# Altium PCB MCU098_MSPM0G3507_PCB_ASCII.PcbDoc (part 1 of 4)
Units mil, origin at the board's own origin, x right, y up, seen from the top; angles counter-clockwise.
Board outline 2310.03 x 4205.03 mil, 4 copper layers (Top Layer, VCC Layer, GND Layer, Bottom Layer), stack 62.4 mil thick; 260 components, 182 nets, 835 pads, 237 vias.
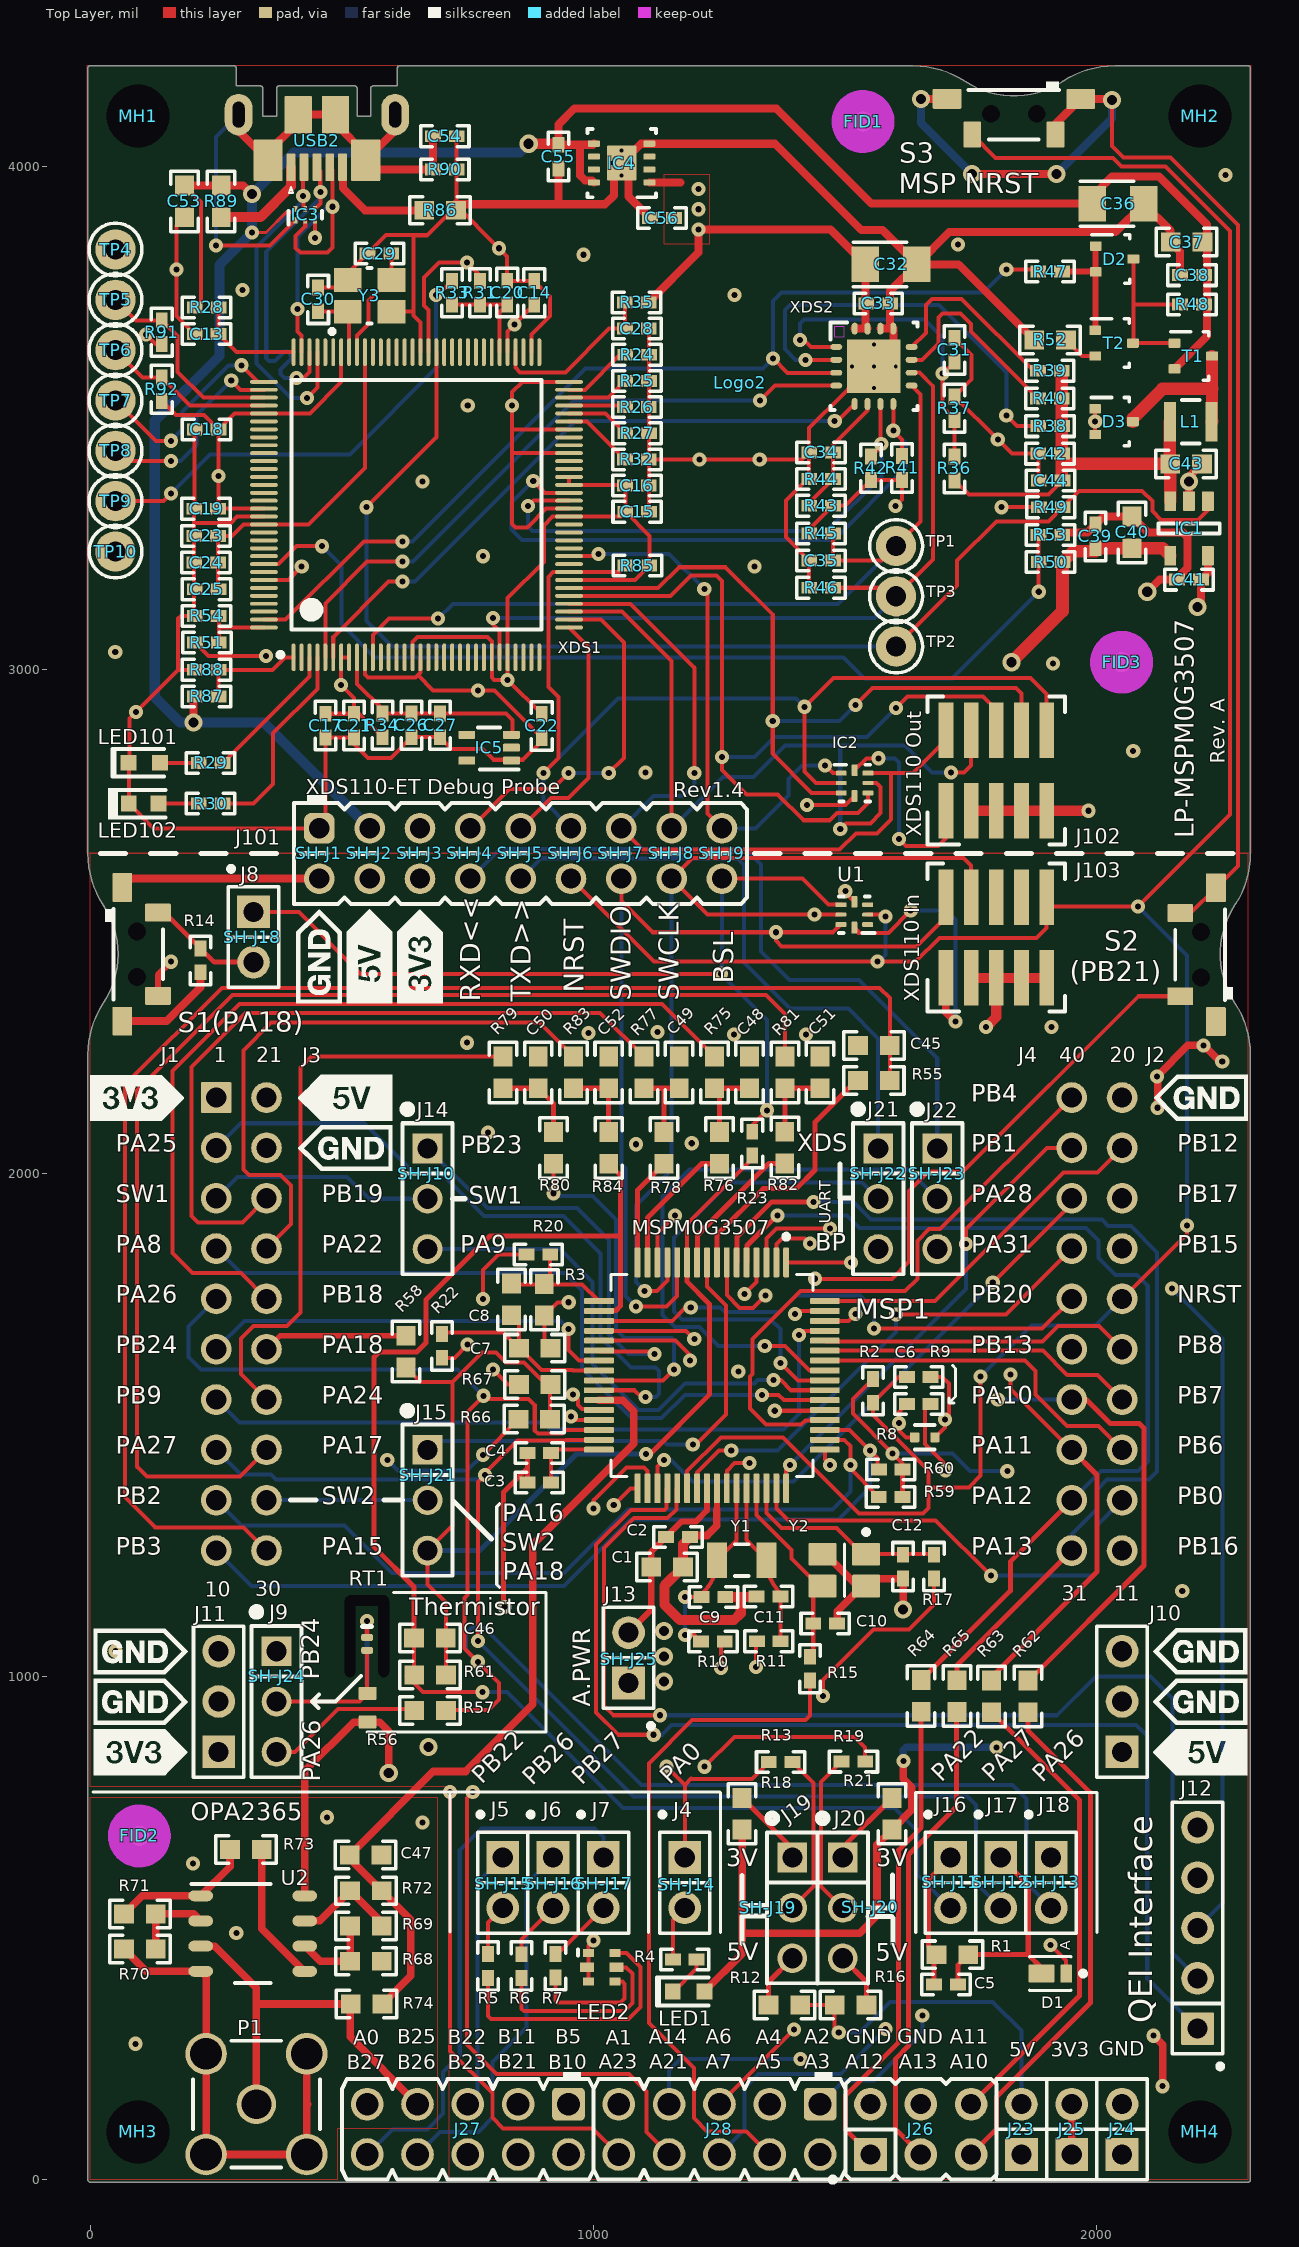
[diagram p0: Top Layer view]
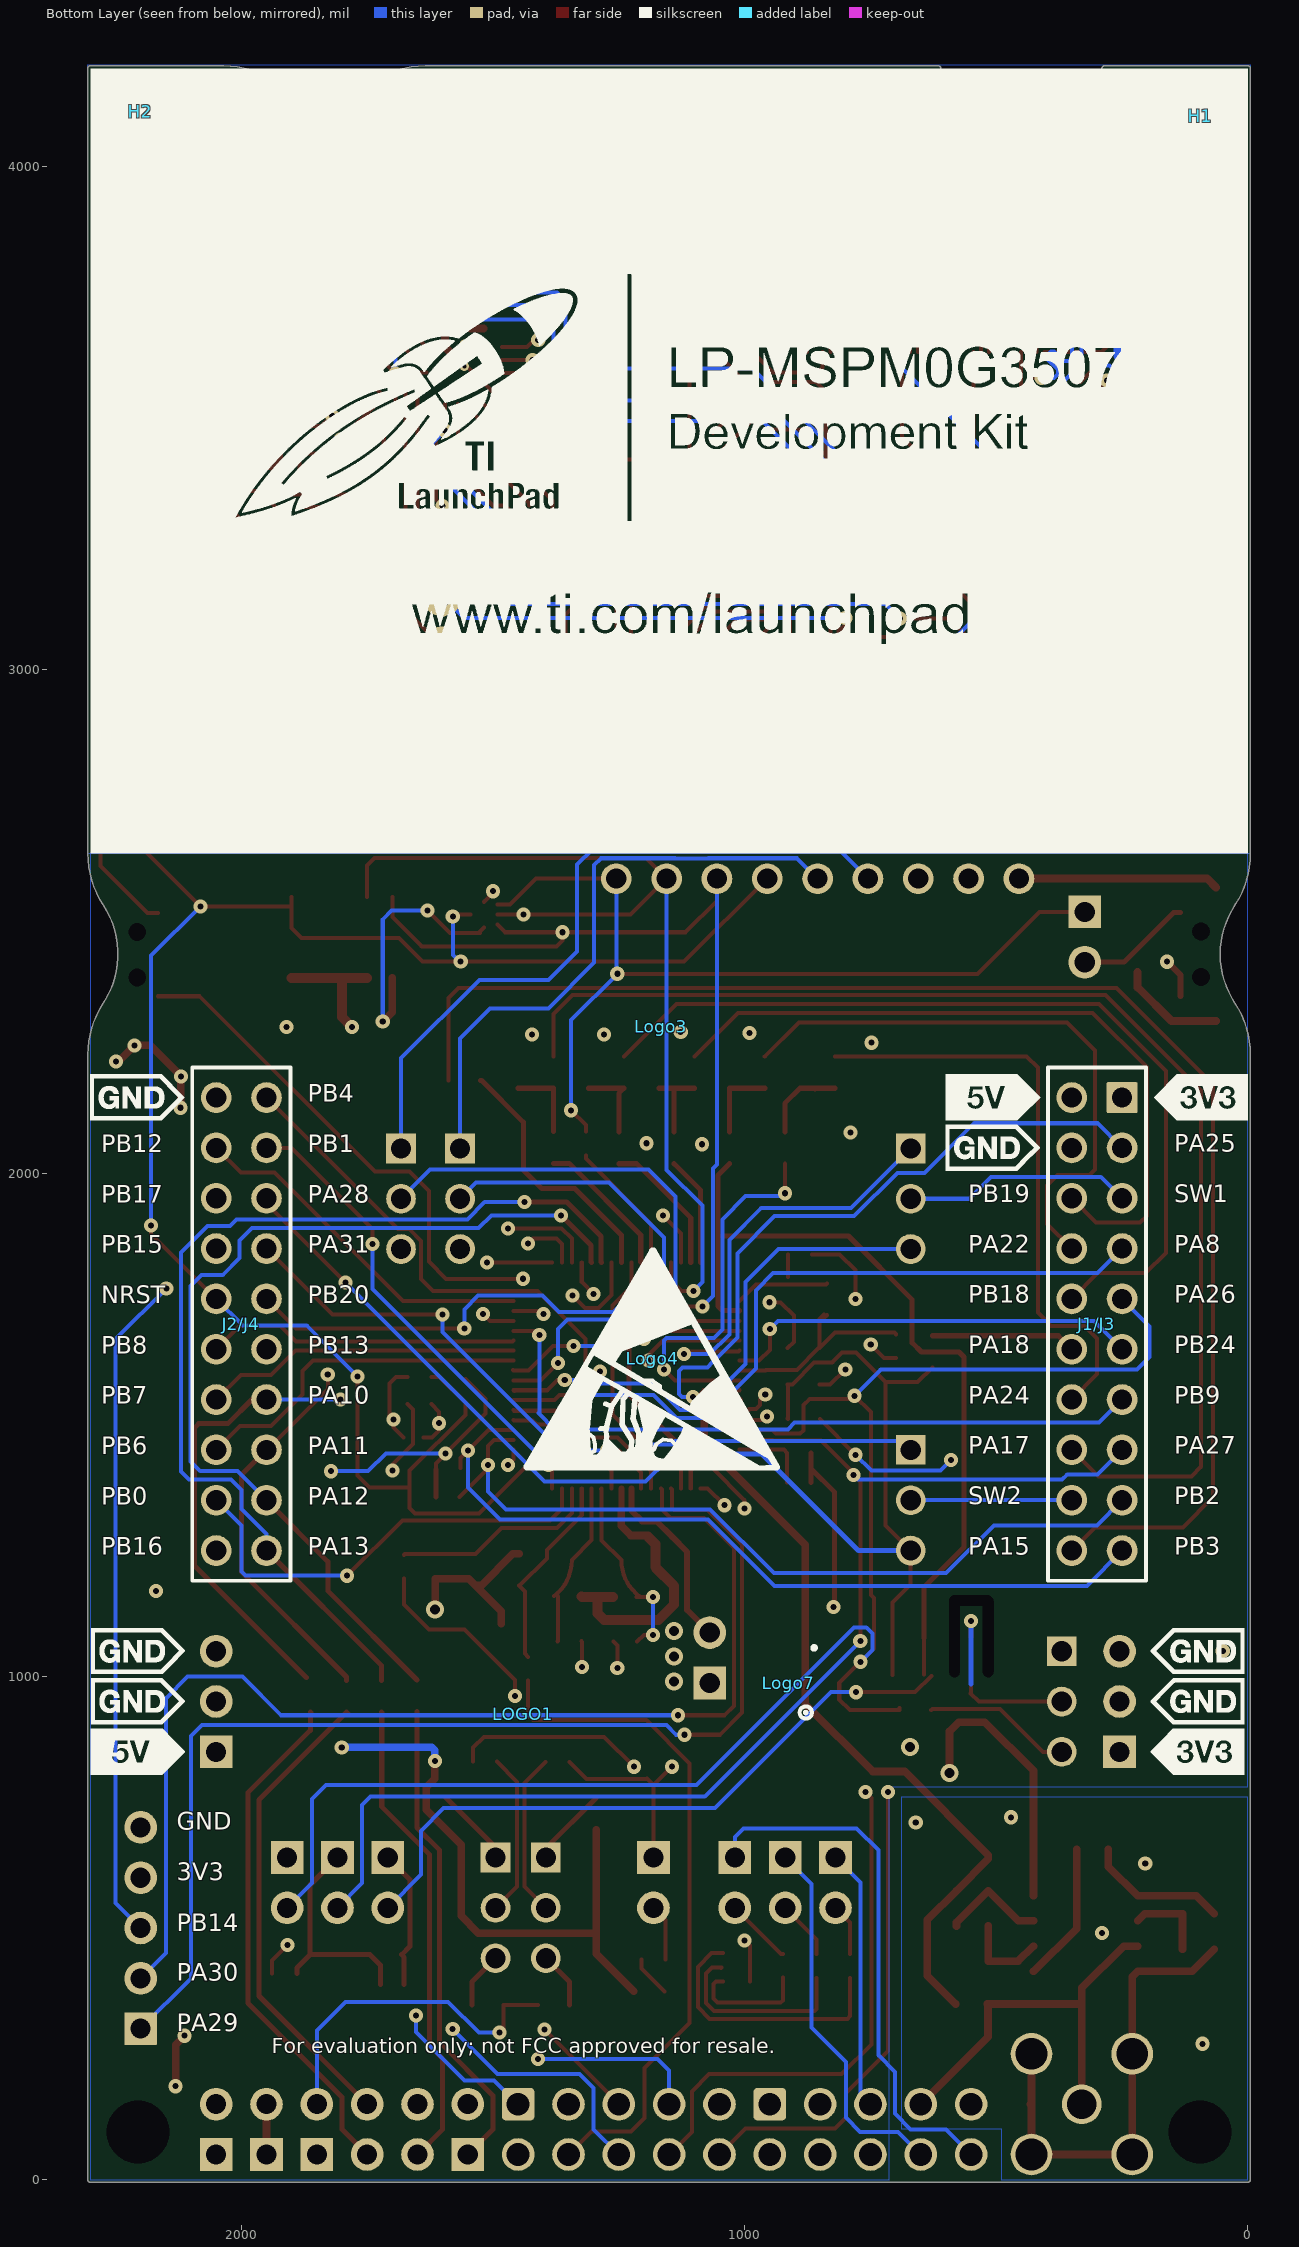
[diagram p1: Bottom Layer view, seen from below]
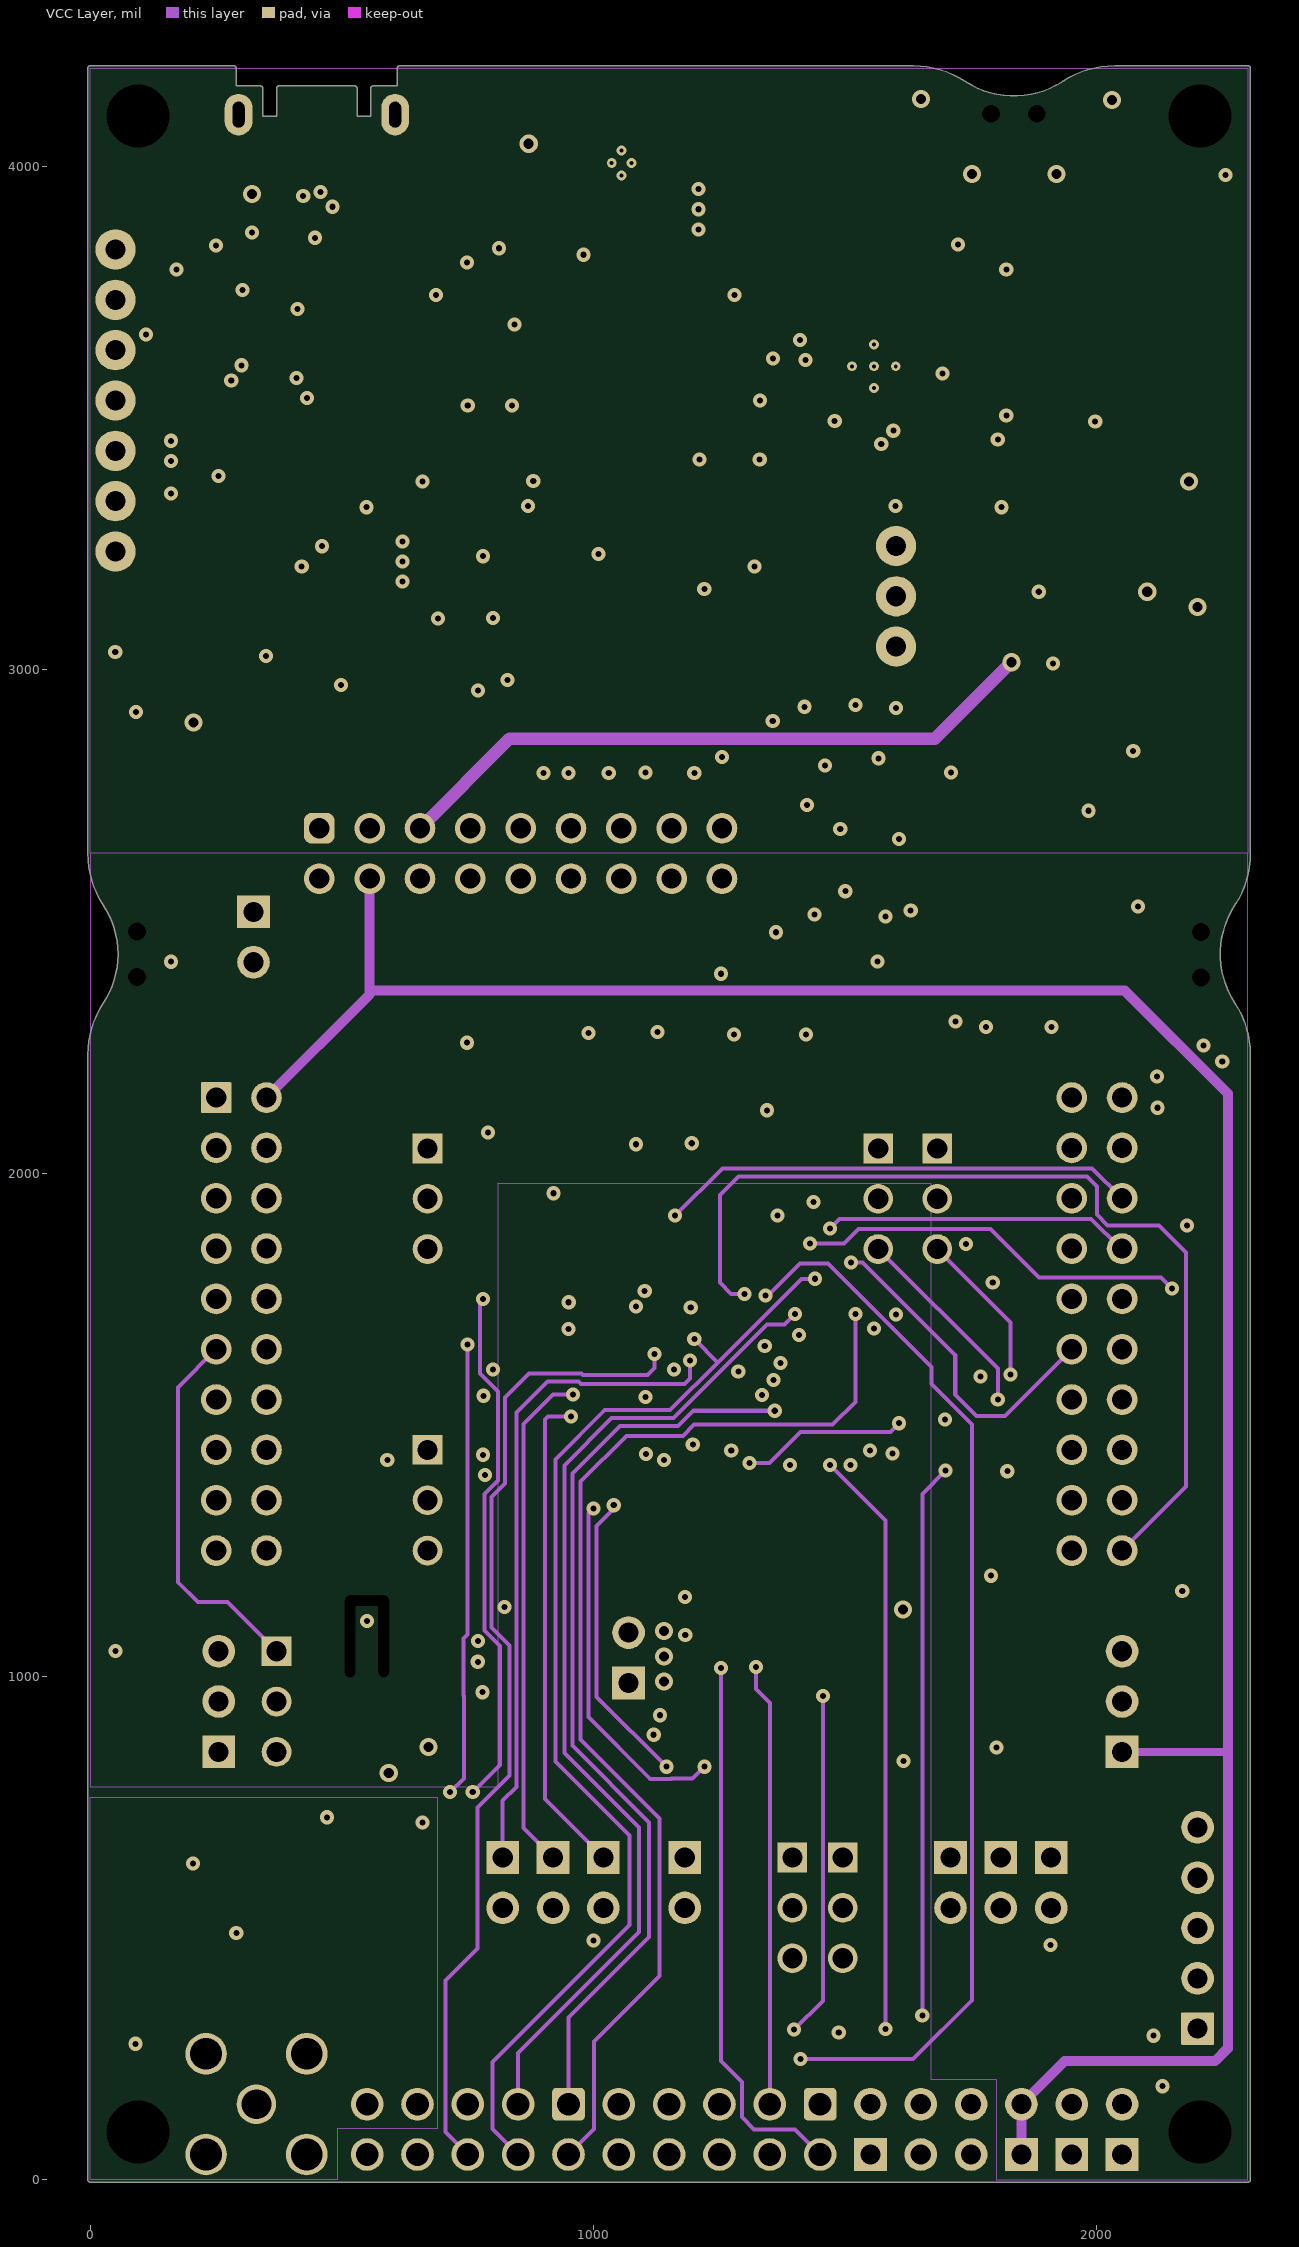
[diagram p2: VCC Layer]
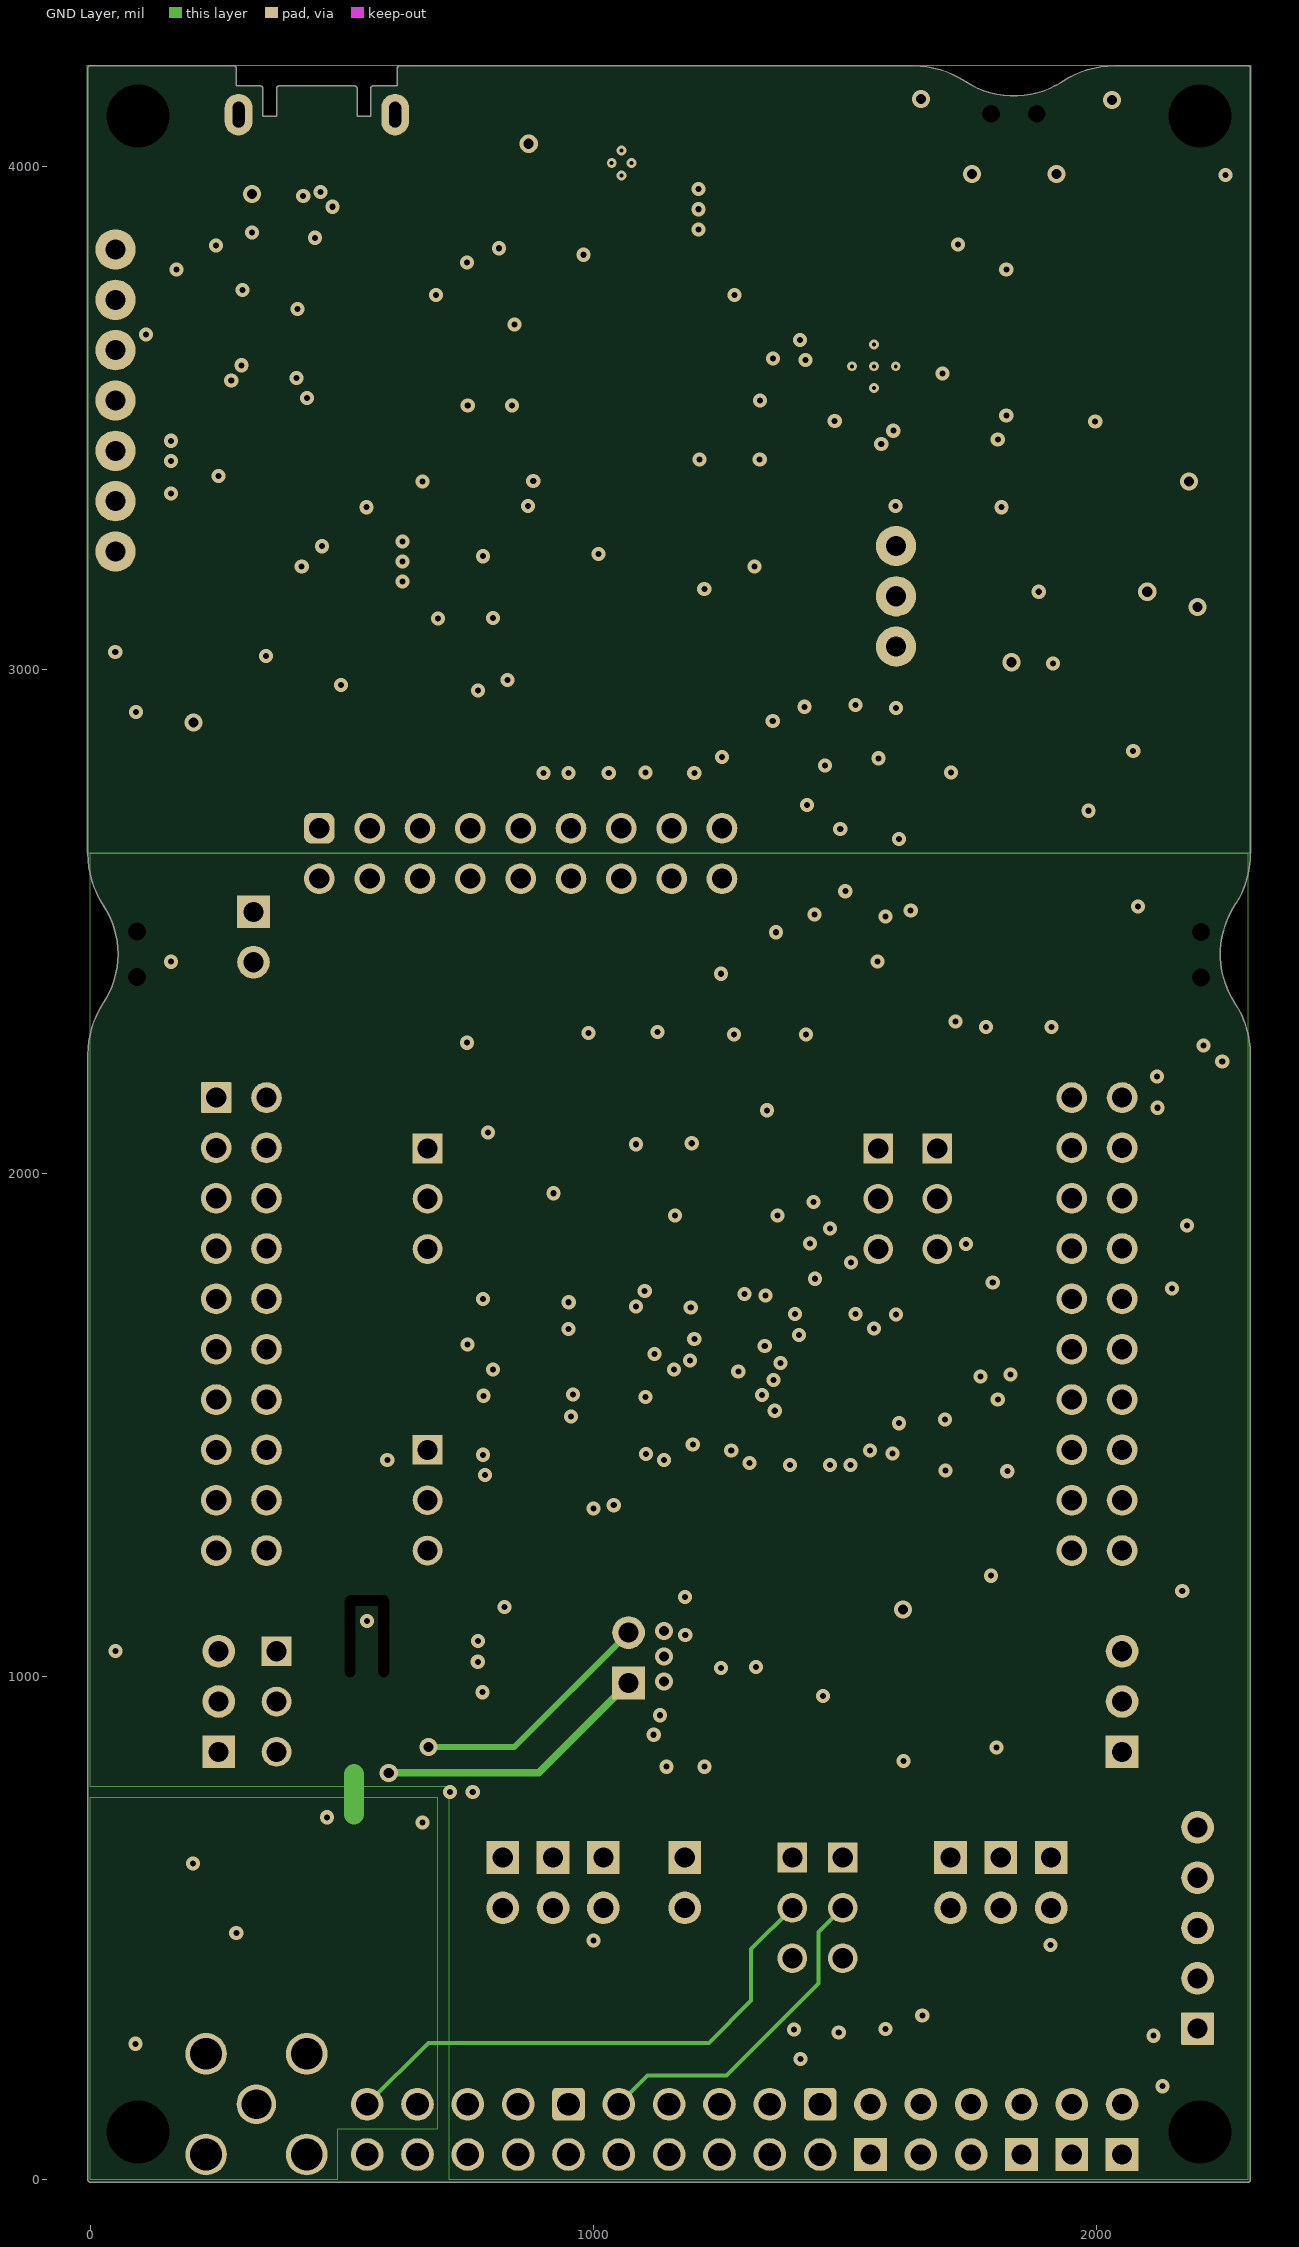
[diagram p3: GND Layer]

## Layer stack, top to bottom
Top Solder: solder mask 0.9843, SM-004, Dk 4
Top Layer: signal copper 1.4
Dielectric 2: core 8.4, FR-4, Dk 4.2
VCC Layer: signal copper 1.4
Dielectric1: prepreg 40, FR-4, Dk 4.2
GND Layer: signal copper 1.4
Dielectric 3: core 8.4, FR-4, Dk 4.2
Bottom Layer: signal copper 1.4
Bottom Solder: solder mask 0.9843, SM-004, Dk 4

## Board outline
-5.01,0 -5.01,2235 cw(c181.67,2235) 25.81,2337.76 ccw(c-121.67,2435) 25.83,2337.79 ccw(c-121.67,2435) 54.99,2435 ccw(c-121.67,2435) 25.88,2532.14 cw(c30,2535) 25.81,2532.24 cw(c181.67,2635) -5.01,2635 -5.01,4195 cw(c0,4195) 0,4200.02 285,4200.02 cw(c285,4195) 290.02,4195 290.02,4160.02 338,4160.02 cw(c338,4155) 343.02,4155 343.02,4100.02 369.99,4100.02 369.99,4155 cw(c375,4155) 375,4160.02 525,4160.02 cw(c525,4155) 530.02,4155 530.02,4100.02 556.99,4100.02 556.99,4155 cw(c562,4155) 562,4160.02 609.99,4160.02 609.99,4195 cw(c615,4195) 615,4200.02 1635,4200.02 cw(c1635,4013.33) 1737.76,4169.19 ccw(c1835,4316.67) 1737.79,4169.17 ccw(c1835,4316.67) 1932.14,4169.12 ccw(c1835,4316.67) 1932.24,4169.18 1932.24,4169.19 cw(c2035,4013.33) 2035,4200.02 2300,4200.02 cw(c2300,4195) 2305.02,4195 2305.02,2635 cw(c2118.33,2635) 2274.19,2532.24 cw(c2270,2535) 2274.17,2532.21 cw(c2421.67,2435) 2274.19,2532.24 2274.17,2532.21 ccw(c2421.67,2435) 2274.12,2337.86 cw(c2270,2335) 2274.19,2337.76 cw(c2118.33,2235) 2305.02,2235 2305.02,0.03 cw(c2300,0) 2305.02,0 2305.02,2235 2305.02,0.03 2305.02,0 cw(c2300,0) 2300,-5.01 0,-5.01 cw(c0,0)

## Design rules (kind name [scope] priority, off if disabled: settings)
AcuteAngle [All] p0: scope1count=1 scope1_0_kind=Board scope1_0_value=Board scope2count=1 scope2_0_kind=Board scope2_0_value=Board commentlength=0 minimum=4.50000000000000E+0001
AcuteAngle [All] p1: minimum=4.50000000000000E+0001 checktracksonly=FALSE
AssemblyTestPointUsage [All] p0: scope1count=1 scope1_0_kind=Board scope1_0_value=Board scope2count=1 scope2_0_kind=Board scope2_0_value=Board commentlength=0
AssemblyTestPointUsage [All] p1: valid=2
AssemblyTestpoint [All] p0: scope1count=1 scope1_0_kind=Board scope1_0_value=Board scope2count=1 scope2_0_kind=Board scope2_0_value=Board commentlength=0
BoardOutlineClearance BoardOutlineClearance_MountingHoles [All] p0 off: scope1count=1 scope1_0_kind=Board scope1_0_value=Board scope2count=1 scope2_0_kind=Board scope2_0_value=Board commentlength=86 gap=15 // Protel DXP Scope 1 Expression Was: OnCopper and InComponentClass('Mounting Holes')
BoardOutlineClearance BoardOutlineClearance_Poly [All] p0 off: scope1count=1 scope1_0_kind=Board scope1_0_value=Board scope2count=1 scope2_0_kind=Board scope2_0_value=Board commentlength=58 gap=15 // Protel DXP Scope 1 Expression Was: OnCopper and IsPoly
BoardOutlineClearance [All] p0 off: scope1count=1 scope1_0_kind=Board scope1_0_value=Board scope2count=1 scope2_0_kind=Board scope2_0_value=Board commentlength=172 gap=10 // Protel DXP Scope 1 Expression Was: OnCopper and Not InComponentClass('Logo') and not InComponentClass('FiducialMark') and not InRegion(1000,500,4000,800) and not InPoly
BoardOutlineClearance BoardOutlineClearance_MountingHoles [OnCopper and InComponentClass('Mounting Holes')] p1: gap=15 ignorepadtopadclearanceinfootprint=FALSE
BoardOutlineClearance BoardOutlineClearance_Poly [OnCopper and IsPoly] p2: gap=15 ignorepadtopadclearanceinfootprint=FALSE
BoardOutlineClearance [OnCopper and Not InComponentClass('Logo') and not InComponentClass('FiducialMark') and not InRegion(1000,500,4000,800) and not InPoly] p3: gap=10 ignorepadtopadclearanceinfootprint=FALSE
Clearance SMD [All] p0 off: scope1count=1 scope1_0_kind=Board scope1_0_value=Board scope2count=1 scope2_0_kind=Board scope2_0_value=Board commentlength=76 gap=10 // Protel DXP Scope 1 Expression Was: InNamedPolygon('GND_LAYER_GND_P-001')
Clearance Clearance_Keepouts [All] p0 off: scope1count=1 scope1_0_kind=Board scope1_0_value=Board scope2count=1 scope2_0_kind=Board scope2_0_value=Board commentlength=99 gap=0 // Protel DXP Scope 2 Expression Was: ((IsTrack Or IsArc) And Not InPoly) And IsFree and IsKeepOut
Clearance Clearance_Poly [All] p0 off: scope1count=1 scope1_0_kind=Board scope1_0_value=Board scope2count=1 scope2_0_kind=Board scope2_0_value=Board commentlength=48 gap=14 // Protel DXP Scope 1 Expression Was: InPolygon
Clearance [All] p0: scope1count=1 scope1_0_kind=Board scope1_0_value=Board scope2count=1 scope2_0_kind=Board scope2_0_value=Board commentlength=0 gap=6
Clearance Clearance_FiducialMark [All] p0 off: scope1count=1 scope1_0_kind=Board scope1_0_value=Board scope2count=1 scope2_0_kind=Board scope2_0_value=Board commentlength=81 gap=0 // Protel DXP Scope 2 Expression Was: IsPad and InComponentClass('FiducialMark')
Clearance SMD [InNamedPolygon('GND_LAYER_GND_P-001')] p1: gap=10 ignorepadtopadclearanceinfootprint=FALSE except(0: Arc-Hole Track-Hole SMDPad-Hole THPad-Hole Via-Hole Fill-Hole Poly-Hole Region-Hole Text-Hole; 20: SMDPad-SMDPad SMDPad-THPad SMDPad-Via SMDPad-Fill SMDPad-Poly SMDPad-Region SMDPad-Text)
Clearance Clearance_FiducialMark [IsKeepOut and InComponentClass('FiducialMark') vs IsPad and InComponentClass('FiducialMark')] p2: gap=0 ignorepadtopadclearanceinfootprint=FALSE
Clearance Clearance_Keepouts [((IsTrack Or IsArc) And Not InPoly) And IsFree and IsKeepOut vs ((IsTrack Or IsArc) And Not InPoly) And IsFree and IsKeepOut] p3: gap=0 ignorepadtopadclearanceinfootprint=FALSE
Clearance Clearance_Poly [InPolygon] p4: gap=14 ignorepadtopadclearanceinfootprint=FALSE except(0: Arc-Hole Track-Hole SMDPad-Hole THPad-Hole Via-Hole Fill-Hole Poly-Hole Region-Hole Text-Hole; 12: Arc-Fill Arc-Poly Arc-Region Track-Fill Track-Poly Track-Region; 15: THPad-THPad; 17: SMDPad-Fill SMDPad-Poly SMDPad-Region)
Clearance [All] p5: gap=6 ignorepadtopadclearanceinfootprint=FALSE
ComponentClearance ComponentClearance_MountingHoles_FiducialMarks [All] p0: scope1count=1 scope1_0_kind=ComponentClass scope1_0_value="Mounting Holes" scope2count=1 scope2_0_kind=ComponentClass scope2_0_value=FiducialMark commentlength=0 gap=0 collisioncheckmode=3
ComponentClearance ComponentClearance_Shunt [All] p0: scope1count=1 scope1_0_kind=ComponentClass scope1_0_value=Header scope2count=1 scope2_0_kind=ComponentClass scope2_0_value=Shunt commentlength=0 gap=0 collisioncheckmode=3
ComponentClearance ComponentClearance_Logo [All] p0: scope1count=1 scope1_0_kind=ComponentClass scope1_0_value=Logo scope2count=1 scope2_0_kind=Board scope2_0_value=Board commentlength=0 gap=0 collisioncheckmode=3
ComponentClearance ComponentClearance_ScrewToNut [All] p0 off: scope1count=1 scope1_0_kind=Board scope1_0_value=Board scope2count=1 scope2_0_kind=Board scope2_0_value=Board commentlength=71 gap=5 collisioncheckmode=3 // Protel DXP Scope 2 Expression Was: (HasFootprint('Keystone_1902C'))
ComponentClearance ComponentClearance_MountingHoles [All] p0: scope1count=1 scope1_0_kind=ComponentClass scope1_0_value="Mounting Holes" scope2count=1 scope2_0_kind=Board scope2_0_value=Board commentlength=0 gap=250 collisioncheckmode=3
ComponentClearance ComponentClearance_SmallPassives [All] p0 off: scope1count=1 scope1_0_kind=Board scope1_0_value=Board scope2count=1 scope2_0_kind=Board scope2_0_value=Board commentlength=508 gap=0 collisioncheckmode=3 // Protel DXP Scope 2 Expression Was: HasFootprint('0201*') or HasFootprint('0402*') or HasFootprint('0508') or HasFootprint('0603*') or HasFootprint('0612') or HasFootprint('0805*') or HasFootprint('0815*') or HasFootprint('0830*') or HasFootprint('1206*') or HasFootprint('1210*') or HasFootprint('1808*') or HasFootprint('1812*') or HasFootprint('1825*') or HasFootprint('2010*') or HasFootprint('2220*') or HasFootprint('2225*') or HasFootprint('2512*') or HasFootprint('2728*') or HasFootprint('3518*')
ComponentClearance ComponentClearance_THtoSMT [All] p0 off: scope1count=1 scope1_0_kind=Board scope1_0_value=Board scope2count=1 scope2_0_kind=Board scope2_0_value=Board commentlength=53 gap=0 collisioncheckmode=3 // Protel DXP Scope 2 Expression Was: IsSMTComponent
ComponentClearance ComponentClearance_THtoTH [All] p0 off: scope1count=1 scope1_0_kind=Board scope1_0_value=Board scope2count=1 scope2_0_kind=Board scope2_0_value=Board commentlength=54 gap=0 collisioncheckmode=3 // Protel DXP Scope 2 Expression Was: IsThruComponent
ComponentClearance [All] p0: scope1count=1 scope1_0_kind=Board scope1_0_value=Board scope2count=1 scope2_0_kind=Board scope2_0_value=Board commentlength=0 gap=0 collisioncheckmode=3
ComponentClearance ComponentClearance_TestPoint [All] p0: scope1count=1 scope1_0_kind=Footprint scope1_0_value=Keystone5001 scope2count=1 scope2_0_kind=Footprint scope2_0_value=Keystone5001 commentlength=0 gap=0 collisioncheckmode=3
ComponentClearance ComponentClearance_2PinHeaders [All] p0: scope1count=1 scope1_0_kind=Footprint scope1_0_value=TSW-102-07-G-S scope2count=1 scope2_0_kind=Footprint scope2_0_value=TSW-102-07-G-S commentlength=0 gap=0 collisioncheckmode=3
ComponentClearance ComponentClearance_Standoffs [All] p0: scope1count=1 scope1_0_kind=Footprint scope1_0_value=KY_MAE-10 scope2count=1 scope2_0_kind=Footprint scope2_0_value=NPTH125mil commentlength=0 gap=0 collisioncheckmode=3
ComponentClearance ComponentClearance_ShuntToShunt [All] p0: scope1count=1 scope1_0_kind=ComponentClass scope1_0_value=Shunt scope2count=1 scope2_0_kind=ComponentClass scope2_0_value=Shunt commentlength=0 gap=0 collisioncheckmode=3
ComponentClearance ComponentClearance_Standoffs [HasFootprint('KY_MAE-10') vs HasFootprint('NPTH125mil')] p1: gap=0 collisioncheckmode=3 verticalgap=0 showdistances=FALSE
ComponentClearance ComponentClearance_2PinHeaders [HasFootprint('TSW-102-07-G-S') vs HasFootprint('TSW-102-07-G-S')] p2: gap=0 collisioncheckmode=3 verticalgap=0 showdistances=FALSE
ComponentClearance ComponentClearance_TestPoint [HasFootprint('Keystone5001') vs HasFootprint('Keystone5001')] p3: gap=0 collisioncheckmode=3 verticalgap=0 showdistances=FALSE
ComponentClearance ComponentClearance_MountingHoles_FiducialMarks [InComponentClass('Mounting Holes') vs InComponentClass('FiducialMark')] p4: gap=0 collisioncheckmode=3 verticalgap=0 showdistances=FALSE
ComponentClearance ComponentClearance_ShuntToShunt [InComponentClass('Shunt') vs InComponentClass('Shunt')] p5: gap=0 collisioncheckmode=3 verticalgap=0 showdistances=FALSE
ComponentClearance ComponentClearance_Shunt [InComponentClass('Header') vs InComponentClass('Shunt')] p6: gap=0 collisioncheckmode=3 verticalgap=0 showdistances=FALSE
ComponentClearance ComponentClearance_Logo [InComponentClass('Logo')] p7: gap=0 collisioncheckmode=3 verticalgap=0 showdistances=FALSE
ComponentClearance ComponentClearance_ScrewToNut [(HasFootprint('NY PMS 440 0025 PH')) vs (HasFootprint('Keystone_1902C'))] p8: gap=5 collisioncheckmode=3 verticalgap=10 showdistances=FALSE
ComponentClearance ComponentClearance_MountingHoles [InComponentClass('Mounting Holes')] p9: gap=250 collisioncheckmode=3 verticalgap=100000 showdistances=FALSE
ComponentClearance ComponentClearance_SmallPassives [HasFootprint('0201*') or HasFootprint('0402*') or HasFootprint('0508') or HasFootprint('0603*') or HasFootprint('0612') or HasFootprint('0805*') or HasFootprint('0815*') or HasFootprint('0830*') or HasFootprint('1206*') or HasFootprint('1210*') or HasFootprint('1808*') or HasFootprint('1812*') or HasFootprint('1825*') or HasFootprint('2010*') or HasFootprint('2220*') or HasFootprint('2225*') or HasFootprint('2512*') or HasFootprint('2728*') or HasFootprint('3518*') vs HasFootprint('0201*') or HasFootprint('0402*') or HasFootprint('0508') or HasFootprint('0603*') or HasFootprint('0612') or HasFootprint('0805*') or HasFootprint('0815*') or HasFootprint('0830*') or HasFootprint('1206*') or HasFootprint('1210*') or HasFootprint('1808*') or HasFootprint('1812*') or HasFootprint('1825*') or HasFootprint('2010*') or HasFootprint('2220*') or HasFootprint('2225*') or HasFootprint('2512*') or HasFootprint('2728*') or HasFootprint('3518*')] p10: gap=0 collisioncheckmode=3 verticalgap=0 showdistances=FALSE
ComponentClearance ComponentClearance_THtoSMT [IsThruComponent vs IsSMTComponent] p11: gap=0 collisioncheckmode=3 verticalgap=0 showdistances=FALSE
ComponentClearance ComponentClearance_THtoTH [IsThruComponent vs IsThruComponent] p12: gap=0 collisioncheckmode=3 verticalgap=0 showdistances=FALSE
ComponentClearance [All] p13: gap=0 collisioncheckmode=3 verticalgap=0 showdistances=FALSE
DiffPairsRouting [All] p0: scope1count=1 scope1_0_kind=Board scope1_0_value=Board scope2count=1 scope2_0_kind=Board scope2_0_value=Board commentlength=0
DiffPairsRouting [All] p1: maxlimit=100 minlimit=10 mostfreqgap=10 toplayer_minwidth=15 toplayer_maxwidth=15 toplayer_prefwidth=15 midlayer1_minwidth=15 midlayer1_maxwidth=15 midlayer1_prefwidth=15 midlayer2_minwidth=15 midlayer2_maxwidth=15 midlayer2_prefwidth=15 bottomlayer_minwidth=15 bottomlayer_maxwidth=15 bottomlayer_prefwidth=15 maxuncoupledlength=1000
FabricationTestPointUsage TestPointUsage [All] p0: scope1count=1 scope1_0_kind=Board scope1_0_value=Board scope2count=1 scope2_0_kind=Board scope2_0_value=Board commentlength=0 valid=2 allowmultiple=FALSE
FabricationTestPointUsage TestPointUsage [All] p1: valid=2 allowmultiple=FALSE
FabricationTestpoint Testpoint [All] p0: scope1count=1 scope1_0_kind=Board scope1_0_value=Board scope2count=1 scope2_0_kind=Board scope2_0_value=Board commentlength=0 side=3 testpointundercomponent=TRUE minsize=40 maxsize=100 preferedsize=60 minholesize=0 maxholesize=40 preferedholesize=32 testpointgrid=1
FabricationTestpoint Testpoint [All] p1: side=3 testpointundercomponent=TRUE minsize=40 maxsize=100 preferedsize=60 minholesize=0 maxholesize=40 preferedholesize=32 testpointgrid=1 allowsidetop=TRUE allowsidebottom=TRUE usegrid=TRUE gridtolerance=0.01
FanoutControl Fanout_LCC [All] p0 off: scope1count=1 scope1_0_kind=Board scope1_0_value=Board scope2count=1 scope2_0_kind=Board scope2_0_value=Board commentlength=69 // Protel DXP Scope 1 Expression Was: IsLCC   Fanout_LCC (Default Rule)
FanoutControl Fanout_BGA [All] p0 off: scope1count=1 scope1_0_kind=Board scope1_0_value=Board scope2count=1 scope2_0_kind=Board scope2_0_value=Board commentlength=69 // Protel DXP Scope 1 Expression Was: IsBGA   Fanout_BGA (Default Rule)
FanoutControl Fanout_SOIC [All] p0 off: scope1count=1 scope1_0_kind=Board scope1_0_value=Board scope2count=1 scope2_0_kind=Board scope2_0_value=Board commentlength=71 // Protel DXP Scope 1 Expression Was: IsSOIC   Fanout_SOIC (Default Rule)
FanoutControl Fanout_Default [All] p0: scope1count=1 scope1_0_kind=Board scope1_0_value=Board scope2count=1 scope2_0_kind=Board scope2_0_value=Board commentlength=30 // Fanout_Default (Default Rule)
FanoutControl Fanout_Small [All] p0 off: scope1count=1 scope1_0_kind=Board scope1_0_value=Board scope2count=1 scope2_0_kind=Board scope2_0_value=Board commentlength=84 // Protel DXP Scope 1 Expression Was: (CompPinCount < 5)   Fanout_Small (Default Rule)
FanoutControl Fanout_LCC [IsLCC] p1: bgadir=Out bgaviamode=Centered fanoutstyle=Auto fanoutdirection=Alternating viagrid=1 // Fanout_LCC (Default Rule)
FanoutControl Fanout_BGA [IsBGA] p2: bgadir=Out bgaviamode=Centered fanoutstyle=Auto fanoutdirection=Alternating viagrid=1 // Fanout_BGA (Default Rule)
FanoutControl Fanout_Default [All] p4: bgadir=Out bgaviamode=Centered fanoutstyle=Auto fanoutdirection=Alternating viagrid=1 // Fanout_Default (Default Rule)
FanoutControl Fanout_Small [(CompPinCount < 5)] p5: bgadir=Out bgaviamode=Centered fanoutstyle=Auto fanoutdirection=OutThenIn viagrid=1 // Fanout_Small (Default Rule)
Height [All] p0: scope1count=1 scope1_0_kind=Board scope1_0_value=Board scope2count=1 scope2_0_kind=Board scope2_0_value=Board commentlength=0
HoleSize [All] p0: scope1count=1 scope1_0_kind=Board scope1_0_value=Board scope2count=1 scope2_0_kind=Board scope2_0_value=Board commentlength=0 absolutevalues=TRUE maxlimit=251 minlimit=7.87 maxpercent=80.000 minpercent=20.000
HoleSize [All] p1: absolutevalues=TRUE maxlimit=251 minlimit=7.87 maxpercent=80.000 minpercent=20.000
HoleToHoleClearance [All] p0: scope1count=1 scope1_0_kind=Board scope1_0_value=Board scope2count=1 scope2_0_kind=Board scope2_0_value=Board commentlength=0
LayerPairs [All] p0: scope1count=1 scope1_0_kind=Board scope1_0_value=Board scope2count=1 scope2_0_kind=Board scope2_0_value=Board commentlength=0 enforce=TRUE
MinimumAnnularRing MinimumAnnularRing_ThermalPadVias [All] p0 off: scope1count=1 scope1_0_kind=Board scope1_0_value=Board scope2count=1 scope2_0_kind=Board scope2_0_value=Board commentlength=63 minimumring=5.91 // Protel DXP Scope 1 Expression Was: IsVia and InAnyComponent
MinimumAnnularRing [All] p0: scope1count=1 scope1_0_kind=Board scope1_0_value=Board scope2count=1 scope2_0_kind=Board scope2_0_value=Board commentlength=0 minimumring=6
MinimumAnnularRing MinimumAnnularRing_ThermalPadVias [IsVia and InAnyComponent] p1: minimumring=5.91
MinimumAnnularRing [All] p2: minimumring=6
MinimumSolderMaskSliver MinimumSolderMaskSliver_Logo [All] p0: scope1count=1 scope1_0_kind=ComponentClass scope1_0_value=Logo scope2count=1 scope2_0_kind=ComponentClass scope2_0_value=Logo commentlength=0
MinimumSolderMaskSliver [All] p0: scope1count=1 scope1_0_kind=Board scope1_0_value=Board scope2count=1 scope2_0_kind=Board scope2_0_value=Board commentlength=0
MinimumSolderMaskSliver MinimumSolderMaskSliver_Logo [InComponentClass('Logo') vs InComponentClass('Logo')] p1: minsoldermaskwidth=0.7
MinimumSolderMaskSliver [All] p2: minsoldermaskwidth=3.94
NetAntennae [All] p0: scope1count=1 scope1_0_kind=Board scope1_0_value=Board scope2count=1 scope2_0_kind=Board scope2_0_value=Board commentlength=0
PasteMaskExpansion [All] p0: scope1count=1 scope1_0_kind=Board scope1_0_value=Board scope2count=1 scope2_0_kind=Board scope2_0_value=Board commentlength=0 expansion=0
PlaneClearance [All] p0: scope1count=1 scope1_0_kind=Board scope1_0_value=Board scope2count=1 scope2_0_kind=Board scope2_0_value=Board commentlength=0 clearance=10
PlaneClearance [All] p1: clearance=10
PlaneConnect [All] p0: scope1count=1 scope1_0_kind=Board scope1_0_value=Board scope2count=1 scope2_0_kind=Board scope2_0_value=Board commentlength=0 planeconnectstyle=Relief reliefexpansion=10 reliefentries=4 reliefconductorwidth=10 reliefairgap=10
PlaneConnect [All] p1: planeconnectstyle=Relief reliefexpansion=10 reliefentries=4 reliefconductorwidth=10 reliefairgap=10
PolygonConnect PolygonConnect_14 [All] p0 off: scope1count=1 scope1_0_kind=Board scope1_0_value=Board scope2count=1 scope2_0_kind=Board scope2_0_value=Board commentlength=76 connectstyle=Direct reliefconductorwidth=10 reliefentries=4 polygonreliefangle="90 Angle" // Protel DXP Scope 2 Expression Was: IsNamedPolygon('GND_LAYER_GND_P-001')
PolygonConnect PolygonConnect_13 [All] p0 off: scope1count=1 scope1_0_kind=Board scope1_0_value=Board scope2count=1 scope2_0_kind=Board scope2_0_value=Board commentlength=78 connectstyle=Direct reliefconductorwidth=10 reliefentries=4 polygonreliefangle="90 Angle" // Protel DXP Scope 2 Expression Was: IsNamedPolygon('BOTTOM_LAYER_GND_P036')
PolygonConnect PolygonConnect_12 [All] p0 off: scope1count=1 scope1_0_kind=Board scope1_0_value=Board scope2count=1 scope2_0_kind=Board scope2_0_value=Board commentlength=75 connectstyle=Direct reliefconductorwidth=10 reliefentries=4 polygonreliefangle="90 Angle" // Protel DXP Scope 2 Expression Was: IsNamedPolygon('TOP_LAYER_GND_P034')
PolygonConnect PolygonConnect_11 [All] p0 off: scope1count=1 scope1_0_kind=Board scope1_0_value=Board scope2count=1 scope2_0_kind=Board scope2_0_value=Board commentlength=75 connectstyle=Direct reliefconductorwidth=10 reliefentries=4 polygonreliefangle="90 Angle" // Protel DXP Scope 2 Expression Was: IsNamedPolygon('VCC_LAYER_3V3_P032')
PolygonConnect PolygonConnect_10 [All] p0 off: scope1count=1 scope1_0_kind=Board scope1_0_value=Board scope2count=1 scope2_0_kind=Board scope2_0_value=Board commentlength=75 connectstyle=Direct reliefconductorwidth=10 reliefentries=4 polygonreliefangle="90 Angle" // Protel DXP Scope 2 Expression Was: IsNamedPolygon('GND_LAYER_GND_P030')
PolygonConnect PolygonConnect_9 [All] p0 off: scope1count=1 scope1_0_kind=Board scope1_0_value=Board scope2count=1 scope2_0_kind=Board scope2_0_value=Board commentlength=78 connectstyle=Direct reliefconductorwidth=10 reliefentries=4 polygonreliefangle="90 Angle" // Protel DXP Scope 2 Expression Was: IsNamedPolygon('BOTTOM_LAYER_GND_P028')
PolygonConnect PolygonConnect_8 [All] p0 off: scope1count=1 scope1_0_kind=Board scope1_0_value=Board scope2count=1 scope2_0_kind=Board scope2_0_value=Board commentlength=75 connectstyle=Direct reliefconductorwidth=10 reliefentries=4 polygonreliefangle="90 Angle" // Protel DXP Scope 2 Expression Was: IsNamedPolygon('GND_LAYER_GND_P026')
PolygonConnect PolygonConnect_7 [All] p0 off: scope1count=1 scope1_0_kind=Board scope1_0_value=Board scope2count=1 scope2_0_kind=Board scope2_0_value=Board commentlength=75 connectstyle=Direct reliefconductorwidth=10 reliefentries=4 polygonreliefangle="90 Angle" // Protel DXP Scope 2 Expression Was: IsNamedPolygon('VCC_LAYER_GND_P024')
PolygonConnect PolygonConnect_6 [All] p0 off: scope1count=1 scope1_0_kind=Board scope1_0_value=Board scope2count=1 scope2_0_kind=Board scope2_0_value=Board commentlength=75 connectstyle=Relief reliefconductorwidth=10 reliefentries=4 polygonreliefangle="90 Angle" // Protel DXP Scope 2 Expression Was: IsNamedPolygon('TOP_LAYER_GND_P022')
PolygonConnect PolygonConnect_5 [All] p0 off: scope1count=1 scope1_0_kind=Board scope1_0_value=Board scope2count=1 scope2_0_kind=Board scope2_0_value=Board commentlength=82 connectstyle=Direct reliefconductorwidth=10 reliefentries=4 polygonreliefangle="90 Angle" // Protel DXP Scope 2 Expression Was: IsNamedPolygon('BOTTOM_LAYER_XDS_GND_P014')
PolygonConnect PolygonConnect_4 [All] p0 off: scope1count=1 scope1_0_kind=Board scope1_0_value=Board scope2count=1 scope2_0_kind=Board scope2_0_value=Board commentlength=79 connectstyle=Direct reliefconductorwidth=10 reliefentries=4 polygonreliefangle="90 Angle" // Protel DXP Scope 2 Expression Was: IsNamedPolygon('TOP_LAYER_XDS_GND_P010')
PolygonConnect PolygonConnect_3 [All] p0 off: scope1count=1 scope1_0_kind=Board scope1_0_value=Board scope2count=1 scope2_0_kind=Board scope2_0_value=Board commentlength=79 connectstyle=Direct reliefconductorwidth=10 reliefentries=4 polygonreliefangle="90 Angle" // Protel DXP Scope 2 Expression Was: IsNamedPolygon('GND_LAYER_XDS_GND_P008')
PolygonConnect PolygonConnect_2 [All] p0 off: scope1count=1 scope1_0_kind=Board scope1_0_value=Board scope2count=1 scope2_0_kind=Board scope2_0_value=Board commentlength=79 connectstyle=Direct reliefconductorwidth=10 reliefentries=4 polygonreliefangle="90 Angle" // Protel DXP Scope 2 Expression Was: IsNamedPolygon('TOP_LAYER_XDS_VCC_P004')
PolygonConnect PolygonConnect_14 [All vs IsNamedPolygon('GND_LAYER_GND_P-001')] p1: connectstyle=Direct reliefconductorwidth=10 reliefentries=4 polygonreliefangle="90 Angle" airgapwidth=10
PolygonConnect PolygonConnect_13 [All vs IsNamedPolygon('BOTTOM_LAYER_GND_P036')] p2: connectstyle=Direct reliefconductorwidth=10 reliefentries=4 polygonreliefangle="90 Angle" airgapwidth=10
PolygonConnect PolygonConnect_12 [All vs IsNamedPolygon('TOP_LAYER_GND_P034')] p3: connectstyle=Direct reliefconductorwidth=10 reliefentries=4 polygonreliefangle="90 Angle" airgapwidth=10
PolygonConnect PolygonConnect_11 [All vs IsNamedPolygon('VCC_LAYER_3V3_P032')] p4: connectstyle=Direct reliefconductorwidth=10 reliefentries=4 polygonreliefangle="90 Angle" airgapwidth=10
PolygonConnect PolygonConnect_10 [All vs IsNamedPolygon('GND_LAYER_GND_P030')] p5: connectstyle=Direct reliefconductorwidth=10 reliefentries=4 polygonreliefangle="90 Angle" airgapwidth=10
PolygonConnect PolygonConnect_9 [All vs IsNamedPolygon('BOTTOM_LAYER_GND_P028')] p6: connectstyle=Direct reliefconductorwidth=10 reliefentries=4 polygonreliefangle="90 Angle" airgapwidth=10
PolygonConnect PolygonConnect_8 [All vs IsNamedPolygon('GND_LAYER_GND_P026')] p7: connectstyle=Direct reliefconductorwidth=10 reliefentries=4 polygonreliefangle="90 Angle" airgapwidth=10
PolygonConnect PolygonConnect_7 [All vs IsNamedPolygon('VCC_LAYER_GND_P024')] p8: connectstyle=Direct reliefconductorwidth=10 reliefentries=4 polygonreliefangle="90 Angle" airgapwidth=10
PolygonConnect PolygonConnect_6 [All vs IsNamedPolygon('TOP_LAYER_GND_P022')] p9: connectstyle=Relief reliefconductorwidth=10 reliefentries=4 polygonreliefangle="90 Angle" airgapwidth=10
PolygonConnect PolygonConnect_5 [All vs IsNamedPolygon('BOTTOM_LAYER_XDS_GND_P014')] p10: connectstyle=Direct reliefconductorwidth=10 reliefentries=4 polygonreliefangle="90 Angle" airgapwidth=10
PolygonConnect PolygonConnect_4 [All vs IsNamedPolygon('TOP_LAYER_XDS_GND_P010')] p11: connectstyle=Direct reliefconductorwidth=10 reliefentries=4 polygonreliefangle="90 Angle" airgapwidth=10
PolygonConnect PolygonConnect_3 [All vs IsNamedPolygon('GND_LAYER_XDS_GND_P008')] p12: connectstyle=Direct reliefconductorwidth=10 reliefentries=4 polygonreliefangle="90 Angle" airgapwidth=10
PolygonConnect PolygonConnect_2 [All vs IsNamedPolygon('TOP_LAYER_XDS_VCC_P004')] p13: connectstyle=Direct reliefconductorwidth=10 reliefentries=4 polygonreliefangle="90 Angle" airgapwidth=10
RoutingCorners [All] p0: scope1count=1 scope1_0_kind=Board scope1_0_value=Board scope2count=1 scope2_0_kind=Board scope2_0_value=Board commentlength=0 cornerstyle=45-Degree minsetback=100 maxsetback=100
RoutingLayers [All] p0: scope1count=1 scope1_0_kind=Board scope1_0_value=Board scope2count=1 scope2_0_kind=Board scope2_0_value=Board commentlength=0 top layer=Automatic mid layer 1=Automatic mid layer 2=Automatic bottom layer=Automatic
RoutingPriority [All] p0: scope1count=1 scope1_0_kind=Board scope1_0_value=Board scope2count=1 scope2_0_kind=Board scope2_0_value=Board commentlength=0
RoutingTopology [All] p0: scope1count=1 scope1_0_kind=Board scope1_0_value=Board scope2count=1 scope2_0_kind=Board scope2_0_value=Board commentlength=0 topology=Shortest
RoutingVias ThermalPadVias [All] p0 off: scope1count=1 scope1_0_kind=Board scope1_0_value=Board scope2count=1 scope2_0_kind=Board scope2_0_value=Board commentlength=63 holewidth=7.87 width=19.68 viastyle="Through Hole" minholewidth=7.87 minwidth=19.68 maxholewidth=16 maxwidth=30 // Protel DXP Scope 1 Expression Was: IsVia and InAnyComponent
RoutingVias [All] p0: scope1count=1 scope1_0_kind=Board scope1_0_value=Board scope2count=1 scope2_0_kind=Board scope2_0_value=Board commentlength=0 holewidth=12 width=28 viastyle="Through Hole" minholewidth=7.87 minwidth=26 maxholewidth=40 maxwidth=65
RoutingVias ThermalPadVias [IsVia and InAnyComponent] p1: holewidth=7.87 width=19.68 viastyle="Through Hole" minholewidth=7.87 minwidth=19.68 maxholewidth=16 maxwidth=30
RoutingVias [All] p2: holewidth=12 width=28 viastyle="Through Hole" minholewidth=7.87 minwidth=26 maxholewidth=40 maxwidth=65
ShortCircuit [All] p0: scope1count=1 scope1_0_kind=Board scope1_0_value=Board scope2count=1 scope2_0_kind=Board scope2_0_value=Board commentlength=0 allowed=FALSE
SilkToBoardRegionClearance [All] p0 off: scope1count=1 scope1_0_kind=Board scope1_0_value=Board scope2count=1 scope2_0_kind=Board scope2_0_value=Board commentlength=130 // Protel DXP Scope 1 Expression Was: Not ((IsComment or IsDesignator) And (Hide <> 'False')) and not InRegion(1000,500,4000,800)
SilkToBoardRegionClearance [Not ((IsComment or IsDesignator) And (Hide <> 'False')) and not InRegion(1000,500,4000,800)] p1:
SilkToSilkClearance SilkToSilkClearance_Pb-FreeLogo [All] p0 off: scope1count=1 scope1_0_kind=Board scope1_0_value=Board scope2count=1 scope2_0_kind=Board scope2_0_value=Board commentlength=120 // Protel DXP Scope 2 Expression Was: (HasFootprint('Pb-Free_Overlay_Medium') OR HasFootprint('Pb-Free_Overlay_Small'))
SilkToSilkClearance [All] p0: scope1count=1 scope1_0_kind=Board scope1_0_value=Board scope2count=1 scope2_0_kind=Board scope2_0_value=Board commentlength=0
SilkToSilkClearance SilkToSilkClearance_Pb-FreeLogo [(HasFootprint('Pb-Free_Overlay_Medium') OR HasFootprint('Pb-Free_Overlay_Small')) vs (HasFootprint('Pb-Free_Overlay_Medium') OR HasFootprint('Pb-Free_Overlay_Small'))] p1: silktosilkclearance=0
SilkToSilkClearance [All] p2: silktosilkclearance=0
SilkToSolderMaskClearance SilkToComponentPadClearance [All] p0 off: scope1count=1 scope1_0_kind=Board scope1_0_value=Board scope2count=1 scope2_0_kind=Board scope2_0_value=Board commentlength=87 // Protel DXP Scope 1 Expression Was: (IsPad or IsFill or IsRegion) and InAnycomponent
SilkToSolderMaskClearance "Silk to Solder Mask Opening" [All] p0: scope1count=1 scope1_0_kind=Board scope1_0_value=Board scope2count=1 scope2_0_kind=Board scope2_0_value=Board commentlength=0
SilkToSolderMaskClearance SilkToComponentPadClearance [(IsPad or IsFill or IsRegion) and InAnycomponent] p1: minsilkscreentomaskgap=0 clearancetoexposedcopper=TRUE
SilkToSolderMaskClearance "Silk to Solder Mask Opening" [All] p2: minsilkscreentomaskgap=0 clearancetoexposedcopper=FALSE
SolderMaskExpansion [All] p0: scope1count=1 scope1_0_kind=Board scope1_0_value=Board scope2count=1 scope2_0_kind=Board scope2_0_value=Board commentlength=0 expansion=1.97
SolderMaskExpansion SolderMaskExpansion_via [All] p0 off: scope1count=1 scope1_0_kind=Board scope1_0_value=Board scope2count=1 scope2_0_kind=Board scope2_0_value=Board commentlength=44 expansion=-17 // Protel DXP Scope 1 Expression Was: isvia
SolderMaskExpansion SolderMaskExpansion_via [isvia] p1: expansion=-17 istentingtop=FALSE
SolderMaskExpansion [All] p2: expansion=1.97 istentingtop=FALSE
UnRoutedNet [All] p0: scope1count=1 scope1_0_kind=Board scope1_0_value=Board scope2count=1 scope2_0_kind=Board scope2_0_value=Board commentlength=0
UnpouredPolygon [All] p0: scope1count=1 scope1_0_kind=Board scope1_0_value=Board scope2count=1 scope2_0_kind=Board scope2_0_value=Board commentlength=0
Width [All] p0: scope1count=1 scope1_0_kind=Board scope1_0_value=Board scope2count=1 scope2_0_kind=Board scope2_0_value=Board commentlength=0 maxlimit=100 minlimit=6 preferedwidth=10
Width [All] p1: maxlimit=100 minlimit=6 preferedwidth=10 checkconnectedcopper=TRUE
14 further rules are at their usual default settings.

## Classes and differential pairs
component class MCU098_07_Hardware: "30N.C. ROUTE" !PCB FID1 FID2 FID3 H1 H2 LOGO1 Logo2 Logo3 Logo4 Logo6 Logo7 MH1 MH2 MH3 MH4 SH-J1 SH-J2 SH-J3 SH-J4 SH-J5 SH-J6 SH-J7 SH-J8 SH-J9 SH-J10 SH-J11 SH-J12 SH-J13 SH-J14 SH-J15 SH-J16 SH-J17 SH-J18 SH-J19 SH-J20 SH-J21 SH-J22 SH-J23 SH-J24 SH-J25 SH-J101A SH-J101B SH-J101C SH-J101D SH-J101E SH-J101F SH-J101G SH-J101H SH-J101I SH-J101J USB1 ZZ1 ZZ2 ZZ3 ZZ4
component class MCU098_06_XDS110-ET_USB_Power: "30N.C. ROUTE" C53 C54 C55 C56 IC3 IC4 R86 R87 R88 R89 R90 R91 R92 TP4 TP5 TP6 TP7 TP8 TP9 TP10 USB2
component class MCU098_05_XDS110_Target_Interface: "30N.C. ROUTE" IC2 J101 J102 J103 R85 U1
component class MCU098_04_XDS110-ET_EnergyTrace: "30N.C. ROUTE" C31 C32 C33 C34 C35 C36 C37 C38 C39 C40 C41 C42 C43 C44 D2 D3 IC1 L1 R36 R37 R38 R39 R40 R41 R42 R43 R44 R45 R46 R47 R48 R49 R50 R51 R52 R53 R54 T1 T2 XDS2
component class MCU098_03_XDS110_Debug_Probe: "30N.C. ROUTE" C13 C14 C15 C16 C17 C18 C19 C20 C21 C22 C23 C24 C25 C26 C27 C28 C29 C30 IC5 LED101 LED102 R24 R25 R26 R27 R28 R29 R30 R31 R32 R33 R34 R35 TP1 TP2 TP3 XDS1 Y3
component class MCU098_02_BoosterPack_Connectors: "30N.C. ROUTE" C45 C46 C47 C48 C49 C50 C51 C52 J1/J3 J2/J4 J9 J12 J14 J15 J23 J24 J25 J26 J27 J28 P1 R55 R56 R57 R58 R59 R60 R61 R62 R63 R64 R65 R66 R67 R68 R69 R70 R71 R72 R73 R74 R75 R76 R77 R78 R79 R80 R81 R82 R83 R84 RT1 U2
component class MCU098_01_MSPM0G3507_Target_Device: "30N.C. ROUTE" C1 C2 C3 C4 C5 C6 C7 C8 C9 C10 C11 C12 D1 J4 J5 J6 J7 J8 J10 J11 J13 J16 J17 J18 J19 J20 J21 J22 LED1 LED2 MSP1 R1 R2 R3 R4 R5 R6 R7 R8 R9 R10 R11 R12 R13 R14 R15 R16 R17 R18 R19 R20 R21 R22 R23 S1 S2 S3 Y1 Y2
component class FiducialMark: "30N.C. ROUTE" FID1 FID2 FID3
component class AssemblyNote: "30N.C. ROUTE" ZZ2 ZZ3 ZZ4 ZZ6
component class Logo: "30N.C. ROUTE" Logo2 Logo3
component class Header: "30N.C. ROUTE" J4 J5 J6 J7 J8 J9 J10 J11 J12 J13 J14 J15 J16 J17 J18 J19 J20 J21 J22 J23 J24 J25 J26 J27 J28 J101
component class Shunt: SH-J1 SH-J2 SH-J3 SH-J4 SH-J5 SH-J6 SH-J7 SH-J8 SH-J9 SH-J10 SH-J11 SH-J12 SH-J13 SH-J14 SH-J15 SH-J16 SH-J17 SH-J18 SH-J19 SH-J20 SH-J21 SH-J22 SH-J23 SH-J24 SH-J25

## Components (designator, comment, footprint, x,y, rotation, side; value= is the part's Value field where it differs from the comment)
C1 "GRM188R60J106ME84" 0603 1146,1217 r0 top
C2 "GRM155R61H104ME14D" 0402 1167.65,1277 r0 top
C3 "GRM155R60J474KE19D" 0402 892,1385.27 r180 top
C4 "GRM155R61H104ME14D" 0402 892,1444 r180 top
C5 "GRM1555C1E470JA01D" 0402 1700,387.54 r0 top
C6 "GRM155R61C103KA01D" 0402 1646,1595 r0 top
C7 "C1608X5R1E105K080AC" 0603 883,1652 r0 top
C8 "C1608X5R1E105K080AC" 0603 836.63,1749 r90 top
C9 "GRM1555C1H220JA01D" 0402 1238,1158 r180 top
C10 "GRM1555C1H220JA01D" 0402 1460,1105 r180 top
C11 "GRM1555C1H220JA01D" 0402 1347.34,1158.65 r0 top
C12 "GRM1555C1H220JA01D" 0402 1615,1218 r90 top
C13 "GRM155R70J104KA01D" 0402 231,3667 r180 top
C14 "GRM155R71E103KA01D" 0402 882,3749 r90 top
C15 "GRM155R71E103KA01D" 0402 1086.5,3314 r0 top
C16 "GRM155R71E103KA01D" 0402 1086,3366 r0 top
C17 "GRM155R70J104KA01D" 0402 467.5,2889 r270 top
C18 "GRM155R70J104KA01D" 0402 231,3477.61 r180 top
C19 "C1005X5R1E105K050BC" 0402 230,3320 r180 top
C20 "GRM155R70J104KA01D" 0402 828.45,3749.33 r90 top
C21 "C1005X5R1E105K050BC" 0402 524,2889 r270 top
C22 "GRM155R71E103KA01D" 0402 897,2888.38 r270 top
C23 "GRM155R60J225KE95D" 0402 230,3266 r180 top
C24 "GRM155R70J104KA01D" 0402 230,3213 r180 top
C25 "C1005X5R1E105K050BC" 0402 231,3160 r180 top
C26 "GRM155R71E103KA01D" 0402 638,2889.63 r270 top
C27 "GRM155R70J104KA01D" 0402 695,2889.63 r270 top
C28 "GRM155R70J104KA01D" 0402 1086,3678 r0 top
C29 "GRM1555C1H120JA01D" 0402 574.38,3826.97 r180 top
C30 "GRM1555C1H120JA01D" 0402 452.72,3736 r90 top
C31 "GRM1555C1H330JA01D" 0402 1717,3635.62 r90 top
C32 "TAJA475K016RNJ" 3216-18 1591.02,3805.58 r0 top
C33 "GRM155R70J104KA01D" 0402 1565.38,3728 r0 top
C34 "GRM1555C1H330JA01D" 0402 1452,3432 r180 top
C35 "GCM155R71H102KA37D" 0402 1452,3217 r180 top
C36 "TAJA475K016RNJ" 3216-18 2042,3926 r0 top
C37 "GRM188R61C475KAAJ" 0603 2178,3849.87 r0 top
C38 "GRM155R70J104KA01D" 0402 2189,3784 r180 top
C39 "GRM155R70J104KA01D" 0402 1997,3265 r90 top
C40 "GRM188R60J476ME15D" 0603 2070,3273 r90 top
C41 "GRM155R71C224KA12D" 0402 2183,3179 r180 top
C42 "GRM155R71C224KA12D" 0402 1907,3429.35 r180 top
C43 "GRM188R61C475KAAJ" 0603 2177,3409 r180 top
C44 "GRM155R70J104KA01D" 0402 1908,3376 r180 top
C45 "C0603C225K8PACTU" 0603 1557.03,2253.53 r180 top
C46 "C0603C225K8PACTU" 0603 674.76,1076.5 r180 top
C47 "C0603C820K5GACTU" 0603 547.01,644.99 r0 top
C48 "C0603C225K8PACTU" 0603 1310,2200 r90 top
C49 "C0603C225K8PACTU" 0603 1170,2200 r90 top
C50 "C0603C225K8PACTU" 0603 890,2200 r90 top
C51 "C0603C225K8PACTU" 0603 1450,2200 r90 top
C52 "C0603C225K8PACTU" 0603 1030,2200 r90 top
C53 "C0603C225K8PACTU" 0603 187,3930.72 r270 top
C54 "GRM155R71H332KA01D" 0402 704.38,4060 r0 top
C55 "C1005X5R1E105K050BC" 0402 930,4019.58 r270 top
C56 "GRM155R60J225KE95D" 0402 1135.73,3897.58 r180 top
D1 "VEMD4110X01" FP-VEMD4110X01_0805-MFG 1907.5,409.52 r90 top
D2 "BAS40-05W,115" SOT-323 2035,3816.13 r0 top
D3 "BAS40-05W,115" SOT-323 2034,3493 r0 top
FID1 "Fiducial" Fiducial10-30 1535.26,4089.22 r0 top
FID2 "Fiducial" Fiducial10-30 97.5,683 r90 top
FID3 "Fiducial" Fiducial10-30 2049.12,3015 r90 top
H1 "MAE-10" KY_MAE-10 95,4100 r180 bottom
H2 "MAE-10" KY_MAE-10 2201,4108.78 r180 bottom
IC1 "TPS2102DBVR" DBV0005A_N 2183,3280.87 r270 top
IC2 "TPD6E004RSER" RSE0008A 1518.56,2774.88 r0 top
IC3 "TPD4E004DRYR" DRY0006A 427,3904 r90 top
IC4 "TPS73533DRBT" DRB0008A 1055.61,4006.78 r180 top
IC5 "LM4040C25IDCKR" DCK0005A_N 792.34,2845.16 r180 top
J1/J3 "SSQ-110-03-T-D" BoosterPack_40pin_J1J3 300,1700 r180 bottom locked
J2/J4 "SSQ-110-03-T-D" BoosterPack_40pin_J2J4 2000,1700 r180 bottom locked
J4 "90120-0122" CONN_90120-0122 1181.14,590 r270 top
J5 "90120-0122" CONN_90120-0122 819.38,590 r270 top
J6 "90120-0122" CONN_90120-0122 919.38,590 r270 top
J7 "90120-0122" CONN_90120-0122 1019.38,590 r270 top
J8 "90120-0122" CONN_90120-0122 324.12,2468.97 r270 top
J9 "PEC03SAAN" CONN_PEC03SAAN 370,950 r270 top
J10 "PEC03SAAN" PEC03SAAN_Launchpad_5V0 2050,950 r90 top
J11 "PEC03SAAN" PEC03SAAN_Launchpad_3V3 255,950 r90 top
J12 "HTSW-105-07-G-S" Samtec_HTSW-105-07-G-S 2200,500 r90 top net-tie
J13 "90120-0122" CONN_90120-0122 1069.38,1037 r90 top
J14 "PEC03SAAN" CONN_PEC03SAAN 670,1949 r270 top
J15 "PEC03SAAN" CONN_PEC03SAAN 670,1350 r270 top
J16 "90120-0122" CONN_90120-0122 1709,590 r270 top
J17 "90120-0122" CONN_90120-0122 1809,590 r270 top
J18 "90120-0122" CONN_90120-0122 1909,590 r270 top
J19 "PEC03SAAN" CONN_PEC03SAAN 1394.88,540 r270 top
J20 "PEC03SAAN" CONN_PEC03SAAN 1494.88,540 r270 top
J21 "PEC03SAAN" CONN_PEC03SAAN 1565.39,1949 r270 top
J22 "PEC03SAAN" CONN_PEC03SAAN 1682.72,1949 r270 top
J23 "90120-0122" CONN_90120-0122 1850,100 r90 top
J24 "90120-0122" CONN_90120-0122 2050,100 r90 top
J25 "90120-0122" CONN_90120-0122 1950,100 r90 top
J26 "PBC03DAAN" Sullins_PBC03DAAN 1650,100 r90 top
J27 "61301021121" WURTH_61301021121 750,100 r180 top
J28 "61301021121" WURTH_61301021121 1250,100 r180 top
J101 "PEC09DAAN" Sullins_PxC09DAAN 855,2635 r270 top
J102 "FTSH-105-01-L-DV-K" Samtec_FTSH-105-01-x-DV-K 1800,2800 r90 top
J103 "FTSH-105-01-L-DV-K" Samtec_FTSH-105-01-x-DV-K 1800,2468 r90 top
L1 "CBC2518T2R2M" CBC2518 2186.4,3493 r180 top
LED1 "BR1111C-TR" 1111C_Red 1188.79,374 r180 top
LED2 "19-337/R6GHBHC-A01/2T" 19-337_RGB 1016,422 r0 top
LED101 "BR1111C-TR" 1111C_Red 107.12,2815.41 r180 top
LED102 "LTST-C190GKT" LED_LTST-C190 106,2734 r180 top
LOGO1 "CE Mark" CE_Mark_5mm 1440.03,925 r180 bottom
Logo2 "Texas Instruments" TI_Horizontal_Overlay_Small 1291,3570 r90 top
Logo3 "Texas Instruments" TI_Horizontal_Overlay_Medium 1166,2291 r180 bottom
Logo4 "ESD Susceptible" ESD_Overlay_Large 1182.65,1630.69 r180 bottom
Logo6 "FCC disclaimer" FCC_disclaimer 3226,1764 r0 bottom
Logo7 "WEEE logo" WEEE_Minimum 912.57,986.5 r180 bottom
MH1 "MTG_NoPads" NPTH125mil 95,4100 r0 top locked
MH2 "MTG_NoPads" NPTH125mil 2205,4100 r0 top locked
MH3 "MTG_NoPads" NPTH125mil 95,95 r0 top locked
MH4 "MTG_NoPads" NPTH125mil 2205,95 r0 top locked
MSP1 "MSPM0G3507SPM" PM0064A-MFG 1235,1598 r270 top (schematic designator U1)
P1 "5-1814832-1" TE_5-1814832-1 330,150 r0 top
R1 "CRCW06032M37FKEA" 0603 1713,447 r180 top
R2 "CRCW040247K0JNED" 0402 1555,1567.38 r90 top
R3 "RC0603JR-070RL" 0603 902,1748.34 r90 top
R4 "CRCW0402470RJNED" 0402 1181,437.26 r0 top
R5 "CRCW0402220RJNED" 0402 790.16,424.43 r270 top
R6 "CRCW0402330RJNED" 0402 857,424.38 r270 top
R7 "CRCW0402330RJNED" 0402 924,425 r270 top
R8 "ERA-2AEB104X" FP-ERA-2AEB104X_0402-MFG 1658,1475 r0 top
R9 "RC0402JR-070RL" 0402 1646,1541 r180 top
R10 "RC0402JR-070RL" 0402 1237,1069 r180 top
R11 "RC0402JR-070RL" 0402 1348,1069.75 r0 top
R12 "RC0603JR-074K7L" 0603 1379,347 r0 top
R13 "CRCW0402270RJNED" 0402 1371.62,830 r0 top
R14 "CRCW040247K0JNED" 0402 219,2422.62 r90 top
R15 "RC0402JR-070RL" 0402 1430,1015.25 r90 top
R16 "RC0603JR-074K7L" 0603 1510.5,347 r180 top
R17 "RC0402JR-070RL" 0402 1676.38,1218 r90 top
R18 "RC0603JR-0710KL" 0603 1295,727 r270 top
R19 "CRCW0402270RJNED" 0402 1516,830.5 r180 top
R20 "RC0402JR-070RL" 0402 890.04,1838 r0 top
R21 "RC0603JR-0710KL" 0603 1593,727 r270 top
R22 "RC0402JR-070RL" 0402 699,1656.63 r90 top
R23 "RC0402JR-070RL" 0402 1315.24,2058.54 r270 top
R24 "CRCW04021K00JNED" 0402 1086.37,3626 r0 top
R25 "CRCW04021K00JNED" 0402 1086.37,3574 r0 top
R26 "CRCW04021K00JNED" 0402 1086,3522 r0 top
R27 "CRCW04021K00JNED" 0402 1086.37,3470 r0 top
R28 "CRCW0402100RJNED" 0402 231,3720 r0 top
R29 "CRCW0402470RJNED" 0402 239,2815 r0 top
R30 "CRCW0402470RJNED" 0402 239,2734 r0 top
R31 "CRCW040210K0JNED" 0402 774,3749 r90 top
R32 "CRCW04024K87FKED" 0402 1086,3418 r180 top
R33 "CRCW0402100RJNED" 0402 718.87,3749 r270 top
R34 "CRCW04021K00JNED" 0402 580.4,2889.63 r270 top
R35 "CRCW040251R0JNED" 0402 1085.38,3730 r0 top
R36 "RC0402FR-07220KL" 0402 1717,3400 r270 top
R37 "RC0402FR-07220KL" 0402 1717,3519.62 r270 top
R38 "ERJ-2RKF3301X" 0402 1907,3484 r0 top
R39 "CRCW04022K20FKED" 0402 1906.38,3594.2 r0 top
R40 "CRCW04026K81FKED" 0402 1906.38,3539 r0 top
R41 "CRCW04024K70JNED" 0402 1613,3401 r270 top
R42 "CRCW04024K70JNED" 0402 1551,3400.35 r270 top
R43 "RC0402FR-07220KL" 0402 1452,3326 r0 top
R44 "RC0402FR-07220KL" 0402 1452,3379 r0 top
R45 "RC0402FR-0747KL" 0402 1452,3271 r180 top
R46 "RC0402FR-0747KL" 0402 1452,3163 r0 top
R47 "RC0402FR-07820RL" 0402 1907,3791 r180 top
R48 "CRCW0402470RJNED" 0402 2189,3726 r0 top
R49 "RC0402FR-0747KL" 0402 1908.38,3323 r0 top
R50 "RC0402FR-07220KL" 0402 1908,3214 r0 top
R51 "RC0402FR-07220KL" 0402 231.62,3054 r180 top
R52 "RC0603JR-070RL" 0603 1907,3655.41 r0 top
R53 "RC0402FR-07220KL" 0402 1907.62,3268 r180 top
R54 "RC0402FR-07220KL" 0402 231,3107 r0 top
R55 "RC0603JR-070RL" 0603 1556.69,2183.75 r0 top
R56 "ERA3ARB103V" ERA3A 551,937.75 r270 top
R57 "RC0603JR-070RL" 0603 674.99,932 r180 top
R58 "RC0603JR-070RL" 0603 627,1645.31 r270 top
R59 "CRCW04024K70JNED" 0402 1590,1356.35 r180 top
R60 "CRCW04024K70JNED" 0402 1590.38,1411.04 r180 top
R61 "RC0603JR-070RL" 0603 674.99,1003.04 r180 top
R62 "RC0603JR-070RL" 0603 1862.84,960.25 r90 top
R63 "RC0603JR-070RL" 0603 1790.84,960.25 r90 top
R64 "RC0603JR-070RL" 0603 1650.84,961.25 r90 top
R65 "RC0603JR-070RL" 0603 1721.84,960.75 r90 top
R66 "RC0603JR-070RL" 0603 882,1511 r0 top
R67 "RC0603JR-070RL" 0603 883,1580 r0 top
R68 "RC0603JR-070RL" 0603 547.5,433.99 r180 top
R69 "RC0603JR-070RL" 0603 547.5,503.99 r0 top
R70 "RC0603JR-070RL" 0603 98.51,457.99 r0 top
R71 "RC0603JR-070RL" 0603 98.51,527.99 r180 top
R72 "RC0603FR-07100RL" 0603 547.5,573.99 r0 top
R73 "RC0603JR-070RL" 0603 309.01,655.99 r0 top
R74 "RC0603JR-070RL" 0603 549,349 r0 top
R75 "RC0603JR-070RL" 0603 1240,2200 r270 top
R76 "RC0603JR-070RL" 0603 1250,2050 r270 top
R77 "RC0603JR-070RL" 0603 1100,2200 r270 top
R78 "RC0603JR-070RL" 0603 1140,2050 r270 top
R79 "RC0603JR-070RL" 0603 820,2200 r270 top
R80 "RC0603JR-070RL" 0603 920,2050 r270 top
R81 "RC0603JR-070RL" 0603 1380,2200 r270 top
R82 "RC0603JR-070RL" 0603 1379.84,2050.75 r270 top
R83 "RC0603JR-070RL" 0603 960,2200 r270 top
R84 "RC0603JR-070RL" 0603 1030,2050 r270 top
R85 "ERJ-2RKF3301X" 0402 1087,3207 r0 top
R86 "RC0603JR-070RL" 0603 694.94,3912.96 r0 top
R87 "RC0402FR-07330KL" 0402 231,2947 r0 top
R88 "RC0402FR-07220KL" 0402 231,3000 r0 top
R89 "RC0603JR-070RL" 0603 260,3930.72 r90 top
R90 "CRCW04021M00FKED" 0402 704.38,3994 r180 top
R91 "CRCW040210K0JNED" 0402 142,3670.76 r90 top
R92 "CRCW040210K0JNED" 0402 142,3557.38 r90 top
RT1 "TMP6131DECT" DEC0002A 550,1064.5 r270 top
S1 "1188E-1K2-V-TR" SW_1188E 106.78,2434.72 r0 top locked
S2 "1188E-1K2-V-TR" SW_1188E 2193,2434 r180 top locked
S3 "1188E-1K2-V-TR" SW_1188E 1835,4091 r270 top locked
SH-J1 "SNT-100-BK-G" SNT-100-BK-G 454.21,2635 r90 top
SH-J2 "SNT-100-BK-G" SNT-100-BK-G 554.21,2635 r90 top
SH-J3 "SNT-100-BK-G" SNT-100-BK-G 654.21,2635 r90 top
SH-J4 "SNT-100-BK-G" SNT-100-BK-G 754.21,2635 r90 top
SH-J5 "SNT-100-BK-G" SNT-100-BK-G 854.21,2635 r90 top
SH-J6 "SNT-100-BK-G" SNT-100-BK-G 954.21,2635 r90 top
SH-J7 "SNT-100-BK-G" SNT-100-BK-G 1054.21,2635 r90 top
SH-J8 "SNT-100-BK-G" SNT-100-BK-G 1154.21,2635 r90 top
SH-J9 "SNT-100-BK-G" SNT-100-BK-G 1254.21,2635 r90 top
SH-J10 "SNT-100-BK-G" SNT-100-BK-G 667,1999 r90 top
SH-J11 "SNT-100-BK-G" SNT-100-BK-G 1708.97,591.06 r90 top
SH-J12 "SNT-100-BK-G" SNT-100-BK-G 1808.97,591.06 r90 top
SH-J13 "SNT-100-BK-G" SNT-100-BK-G 1908.97,591.06 r90 top
SH-J14 "SNT-100-BK-G" SNT-100-BK-G 1184.79,586.37 r90 top
SH-J15 "SNT-100-BK-G" SNT-100-BK-G 820,588 r90 top
SH-J16 "SNT-100-BK-G" SNT-100-BK-G 920,588 r90 top
SH-J17 "SNT-100-BK-G" SNT-100-BK-G 1020,588 r90 top
SH-J18 "SNT-100-BK-G" SNT-100-BK-G 322,2468.97 r90 top
SH-J19 "SNT-100-BK-G" SNT-100-BK-G 1346.21,540 r180 top
SH-J20 "SNT-100-BK-G" SNT-100-BK-G 1549.35,541 r180 top
SH-J21 "SNT-100-BK-G" SNT-100-BK-G 670,1400 r90 top
SH-J22 "SNT-100-BK-G" SNT-100-BK-G 1565.39,1999 r90 top
SH-J23 "SNT-100-BK-G" SNT-100-BK-G 1682,1999 r90 top
SH-J24 "SNT-100-BK-G" SNT-100-BK-G 370,1000 r90 top
SH-J25 "SNT-100-BK-G" SNT-100-BK-G 1069.38,1033.52 r90 top
T1 "DMG1013UW-7" SOT-323 2191.4,3623.41 r0 top
T2 "BC850CW,115" SOT-323 2034,3649 r0 top
TP1 "5001" Keystone5001 1601,3246 r90 top
TP2 "5001" Keystone5001 1601,3046 r90 top
TP3 "5001" Keystone5001 1601,3146 r90 top
TP4 "5001" Keystone5001 50,3835 r90 top
TP5 "5001" Keystone5001 50,3735 r90 top
TP6 "5001" Keystone5001 50,3635 r90 top
TP7 "5001" Keystone5001 50,3535 r90 top
TP8 "5001" Keystone5001 50,3435 r90 top
TP9 "5001" Keystone5001 50,3335 r90 top
TP10 "5001" Keystone5001 50,3235 r90 top
U1 "TPD6E004RSER" RSE0008A 1517.93,2513.49 r180 top
U2 "OPA2365AIDR" D0008A_L 322.66,488.99 r0 top
USB2 "1051640001" Molex_1051640001 450.09,4160.09 r180 top locked
XDS1 "MSP432E401YTPDTR" PDT0128A 648,3328 r90 top (schematic designator MSP1)
XDS2 "MSP430G2452IRSA16R" RSA0016B 1557,3603 r0 top (schematic designator MSP2)
Y1 "X1A0001410014" Epson_FC-135 1294.19,1231 r180 top
Y2 "X1E0000210179" FP-X1E0000210179_TSX-3225-MFG 1498,1211 r180 top
Y3 "NX3225GA-16.000M-STD-CRG-1" NDK_NX3225GA 555,3743 r90 top
ZZ2 "These assemblies must be clean and free from flux and all contaminants. Use of no clean flux is not acceptable." AssemblyNote 145,5140 r0 top
ZZ3 "These assemblies must comply with workmanship standards IPC-A-610 Class 2, unless otherwise specified." AssemblyNote 140,5250 r0 top
ZZ4 "Place a click-in Standoff (MAE-10, KangYang)  in hole MH1/MH2" AssemblyNote 135,5345 r0 top

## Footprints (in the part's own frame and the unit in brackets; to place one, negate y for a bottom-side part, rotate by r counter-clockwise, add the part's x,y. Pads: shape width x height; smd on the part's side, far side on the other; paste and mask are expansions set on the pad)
19-337_RGB [mm] "SMD, 6-Leads, Body 1.6x1.6mm"
  rect 0.55x0.4 smd: 1(-0.675,0.725) 3(-0.675,-0.725) 4(0.675,0.725) 6(0.675,-0.725)
  rect 0.7x0.5 smd: 2(-0.75,0) 5(0.75,0)
  silkscreen extent -1.2,0.6 -1.2,0.9
0402 [mm] "0402 from SM-752 data"
  rect 0.8x0.6 smd: 1(-0.6,0) 2(0.6,0)
  silkscreen extent -1.22,-0.52 1.22,0.52
0603 [mm] "0603 from SM-752 data"
  rect 1x0.95 smd: 1(-0.8,0) 2(0.8,0)
  silkscreen extent -1.52,-0.69 1.52,0.69
1111C_Red [mm] "SMD, 2-Leads, Body 1.6x0.8mm"
  rect 0.8x0.8 smd: 1(-0.8,0) 2(0.8,0)
  silkscreen extent -1,-0.7 1.7,0.7
3216-18 [mm] "Based on AVX recommendation in http://www.avx.com/download/software/literature/AVX-Footprint-Library.pdf"
  rrect7% 1.4x1.8 smd: 1(-1.3,0) 2(1.3,0)
  silkscreen extent -1.9,-1.12 0.8,1.12
AssemblyNote [mil] "Assembly Note"
BoosterPack_40pin_J1J3 [mm] "Receptacle, 2.54mm, 10x2, TH"
  rrect6% 1.55x1.55 hole 1.02: 1(1.27,11.43)
  round 1.55 hole 1.02: 2(1.27,8.89) 3(1.27,6.35) 4(1.27,3.81) 5(1.27,1.27) 6(1.27,-1.27) 7(1.27,-3.81) 8(1.27,-6.35) 9(1.27,-8.89) 10(1.27,-11.43) 21(-1.27,11.43) 22(-1.27,8.89) 23(-1.27,6.35) 24(-1.27,3.81) 25(-1.27,1.27) 26(-1.27,-1.27) 27(-1.27,-3.81) 28(-1.27,-6.35) 29(-1.27,-8.89) 30(-1.27,-11.43)
  silkscreen extent -7.62,-12.95 7.62,12.95
BoosterPack_40pin_J2J4 [mm] "Receptacle, 2.54mm, 10x2, TH"
  round 1.55 hole 1.02: 11(-1.27,-11.43) 12(-1.27,-8.89) 13(-1.27,-6.35) 14(-1.27,-3.81) 15(-1.27,-1.27) 16(-1.27,1.27) 17(-1.27,3.81) 18(-1.27,6.35) 19(-1.27,8.89) 20(-1.27,11.43) 31(1.27,-11.43) 32(1.27,-8.89) 33(1.27,-6.35) 34(1.27,-3.81) 35(1.27,-1.27) 36(1.27,1.27) 37(1.27,3.81) 38(1.27,6.35) 39(1.27,8.89) 40(1.27,11.43)
  silkscreen extent -7.62,-12.95 2.48,12.95
CBC2518 [mm] "Taiyo Yuden"
  rect 0.6x2 smd: 1(-1.05,0) 2(1.05,0)
  silkscreen extent -0.45,-1.1 0.45,1.1
CE_Mark_5mm [mil] "Minimum text height for CE Mark"
CONN_90120-0122 [mm] "Molex"
  rect 1.65x1.65 hole 1.016 mask+0: 1(-1.27,0)
  round 1.65 hole 1.016 mask+0: 2(1.27,0)
  silkscreen extent -3.56,-1.27 2.54,1.27
CONN_PEC03SAAN [mm] "SULLINS"
  rect 1.5x1.5 hole 1.016: 1(-2.54,0)
  round 1.5 hole 1.016: 2(0,0) 3(2.54,0)
  silkscreen extent -4.72,-1.27 3.81,1.27
D0008A_L [mm] "SOIC, 8-Leads, Body 4.9x3.9mm, Pitch 1.27mm, IPC High Density"
  oval 1.25x0.55 smd: 1(-2.625,1.905) 2(-2.625,0.635) 3(-2.625,-0.635) 4(-2.625,-1.905) 5(2.625,-1.905) 6(2.625,-0.635) 7(2.625,0.635) 8(2.625,1.905)
  silkscreen extent -3.1,-2.5 0.9,2.5
DBV0005A_N [mm] "SOT23, 5-Leads, Body 2.9x1.6mm, Pitch 0.95mm, Lead Span 2.8mm, IPC Medium Density"
  rrect17% 1x0.6 smd: 1(-1.375,0.95) 2(-1.375,0) 3(-1.375,-0.95) 4(1.375,-0.95) 5(1.375,0.95)
  silkscreen extent -0.25,-1.55 0.25,1.55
